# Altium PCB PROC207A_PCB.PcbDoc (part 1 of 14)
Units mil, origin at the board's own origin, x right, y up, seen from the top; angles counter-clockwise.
Board outline 4094.49 x 3724.79 mil, 8 copper layers (Top Layer, L2_GND1, L3_SIG1, L4_PWR1, L5_PWR2, L6_SIG2, L7_GND2, Bottom Layer), stack 58.1 mil thick; 584 components, 399 nets, 8440 pads, 5258 vias.
Unrouted connection lines stored in the file: 9.
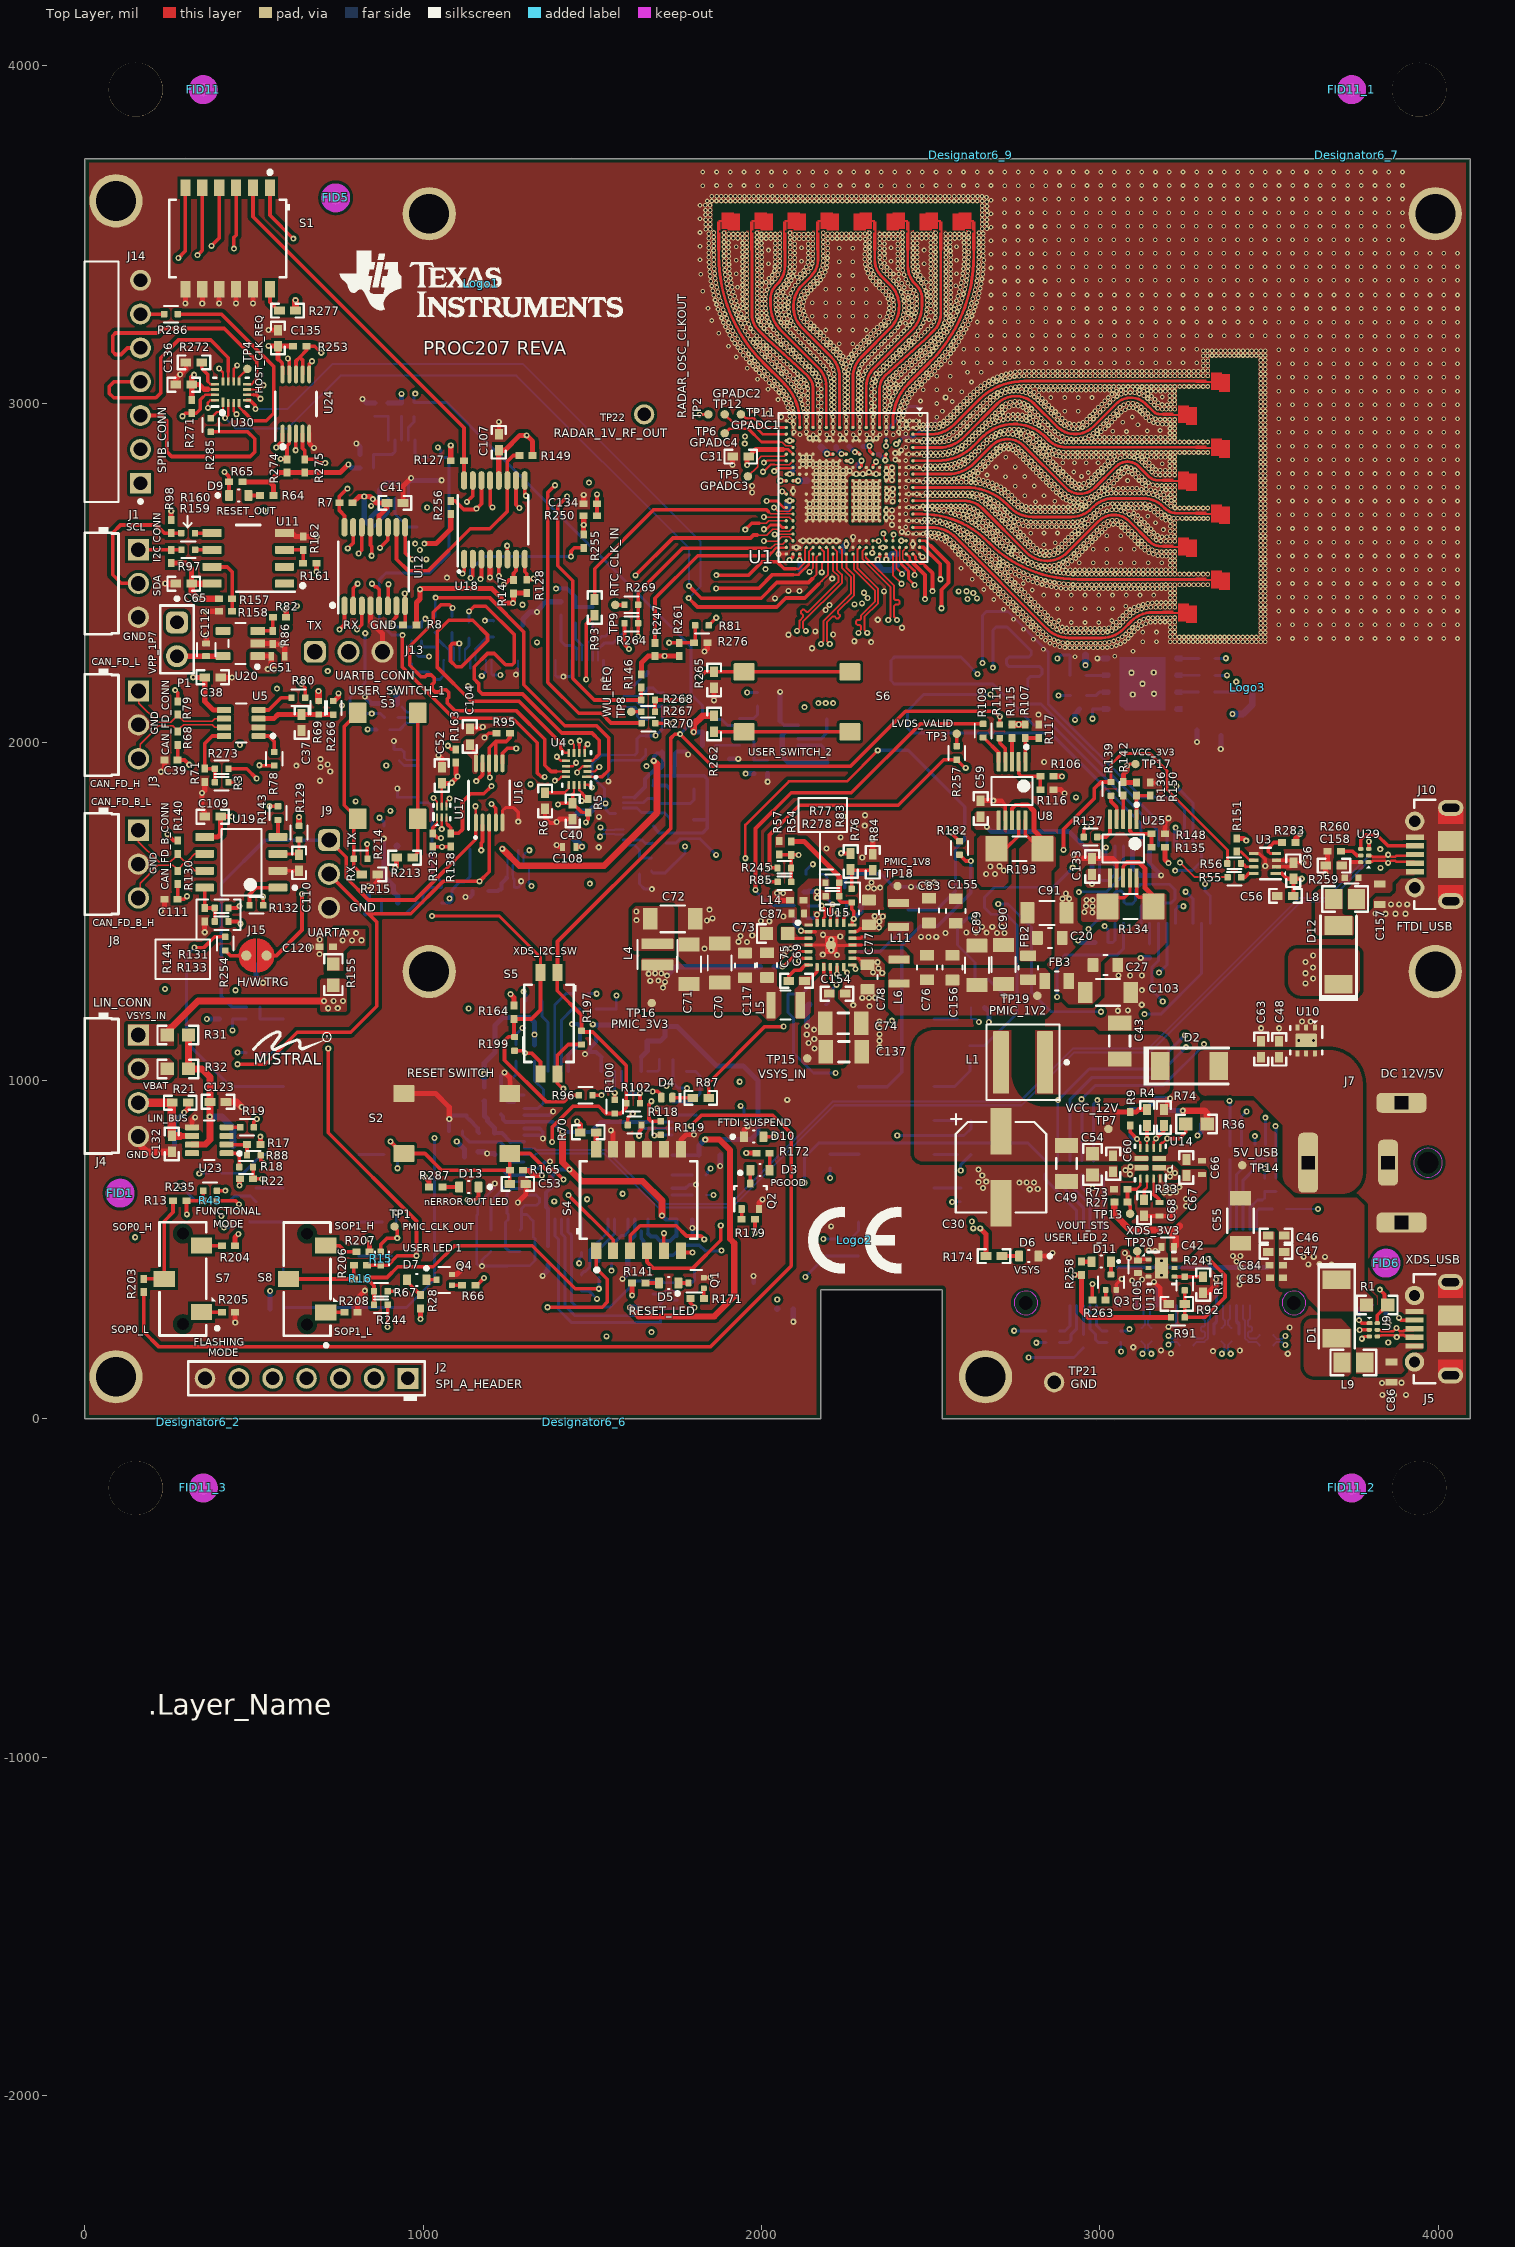
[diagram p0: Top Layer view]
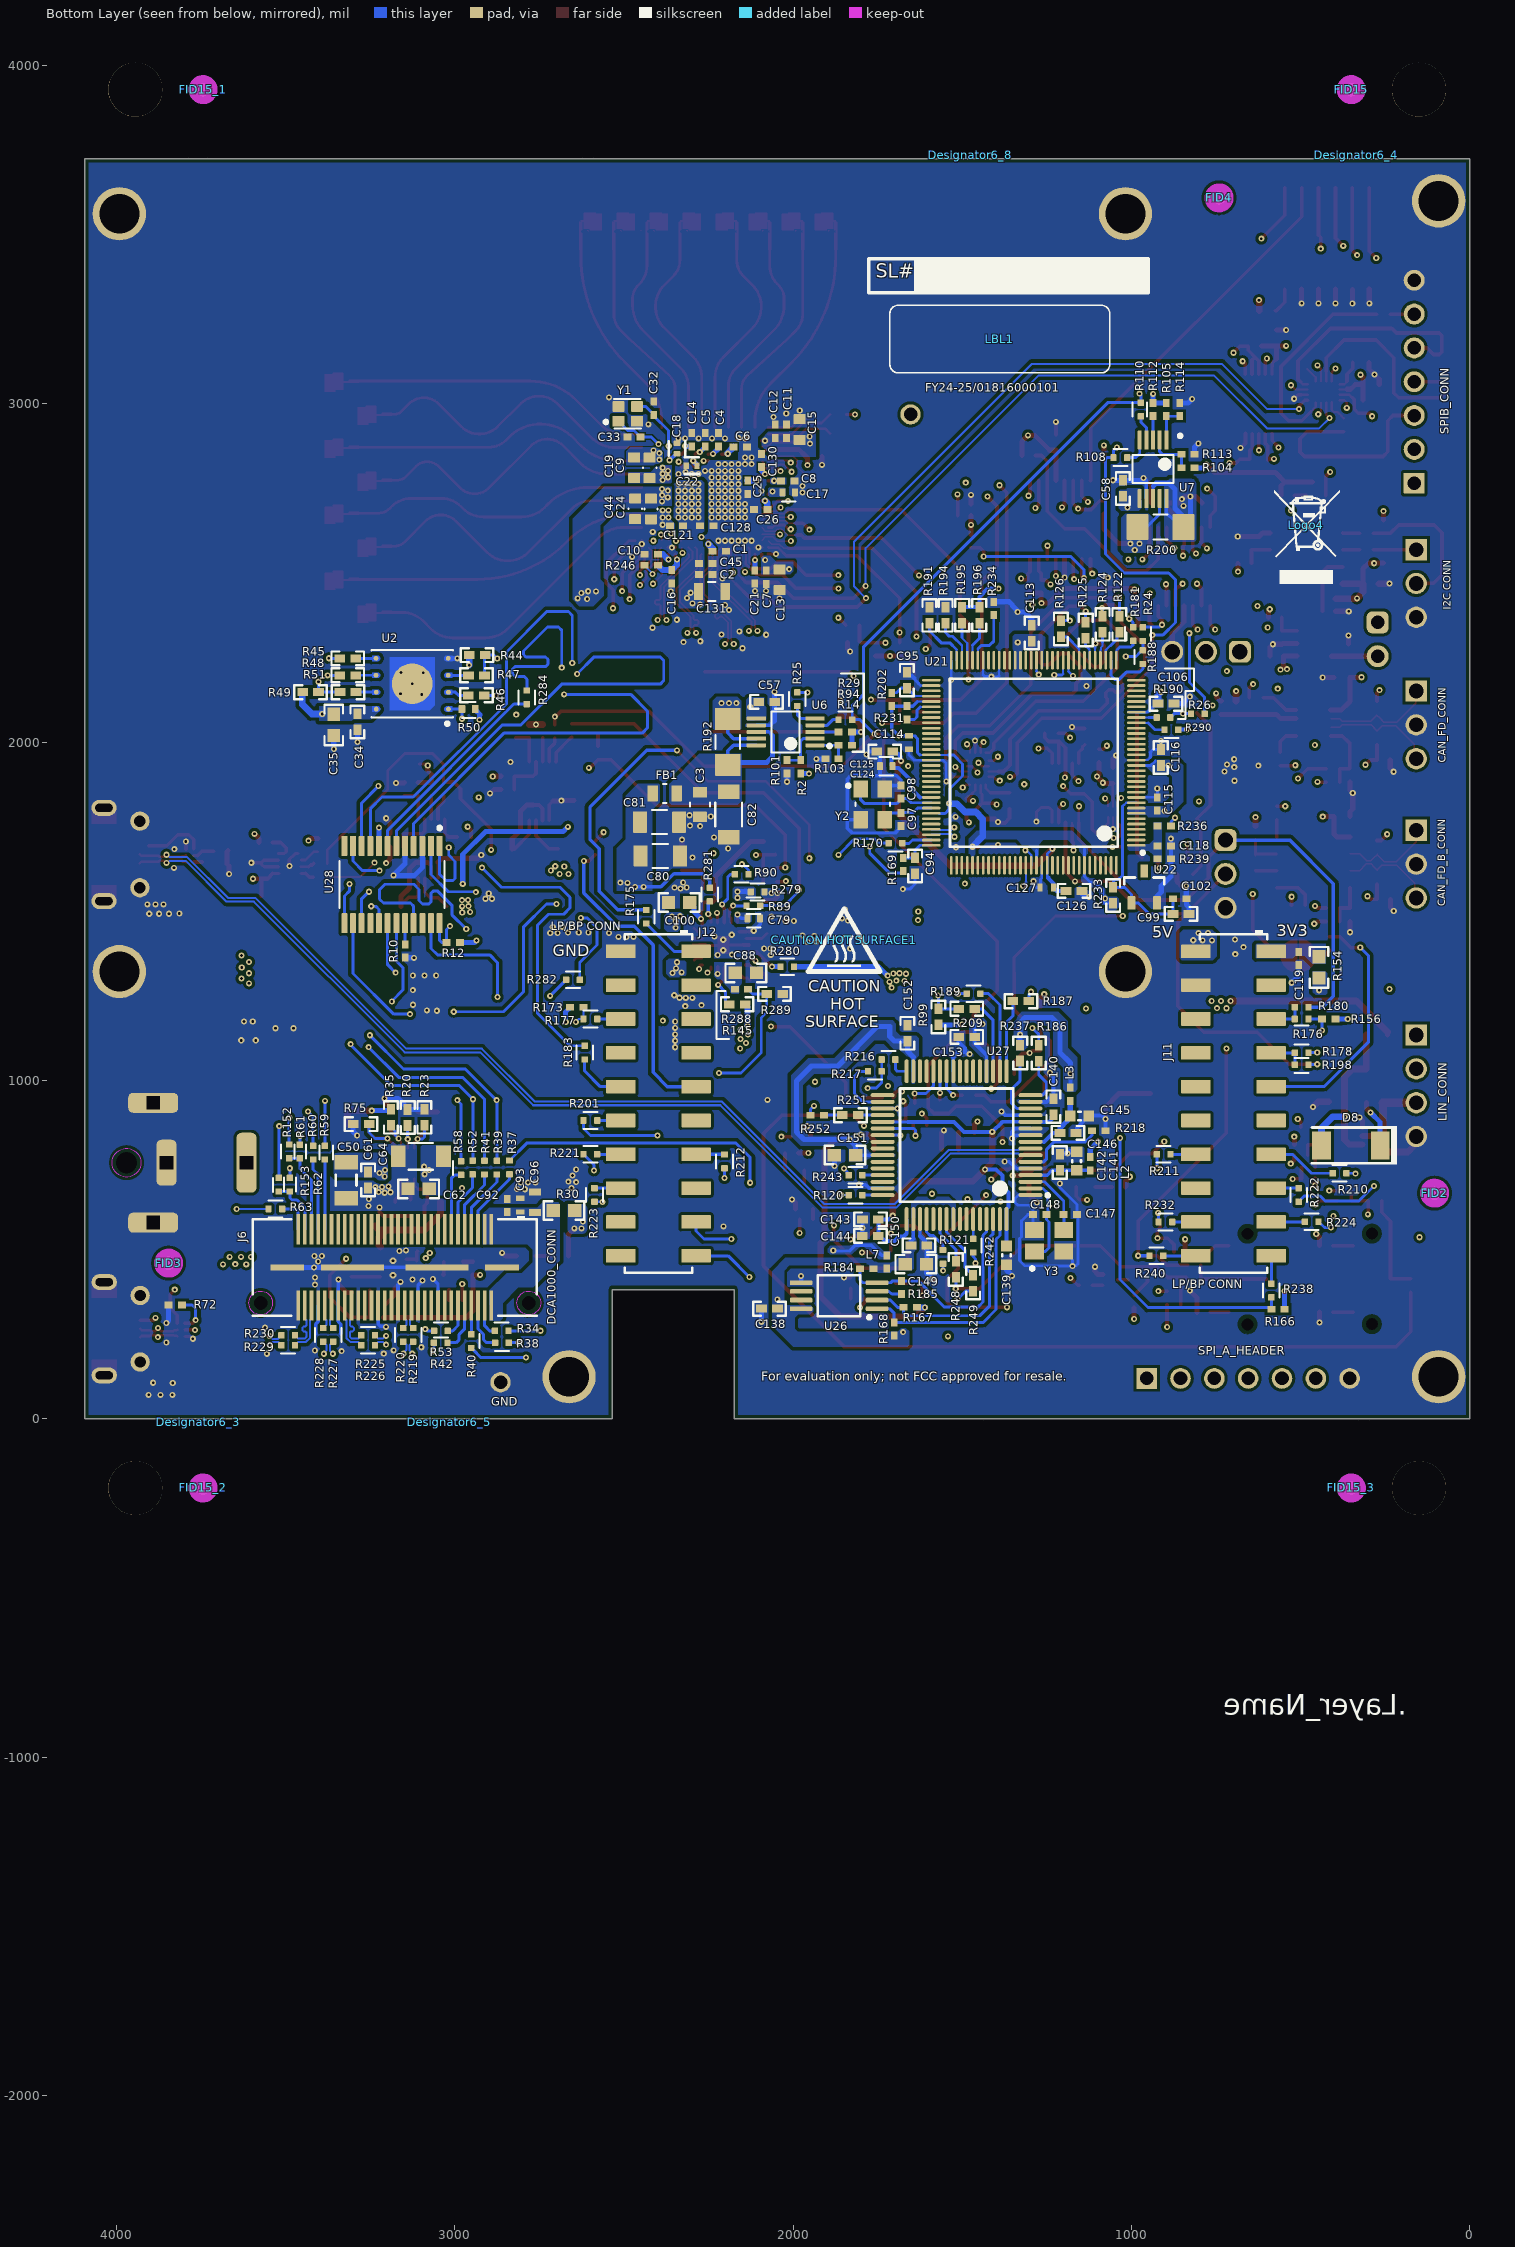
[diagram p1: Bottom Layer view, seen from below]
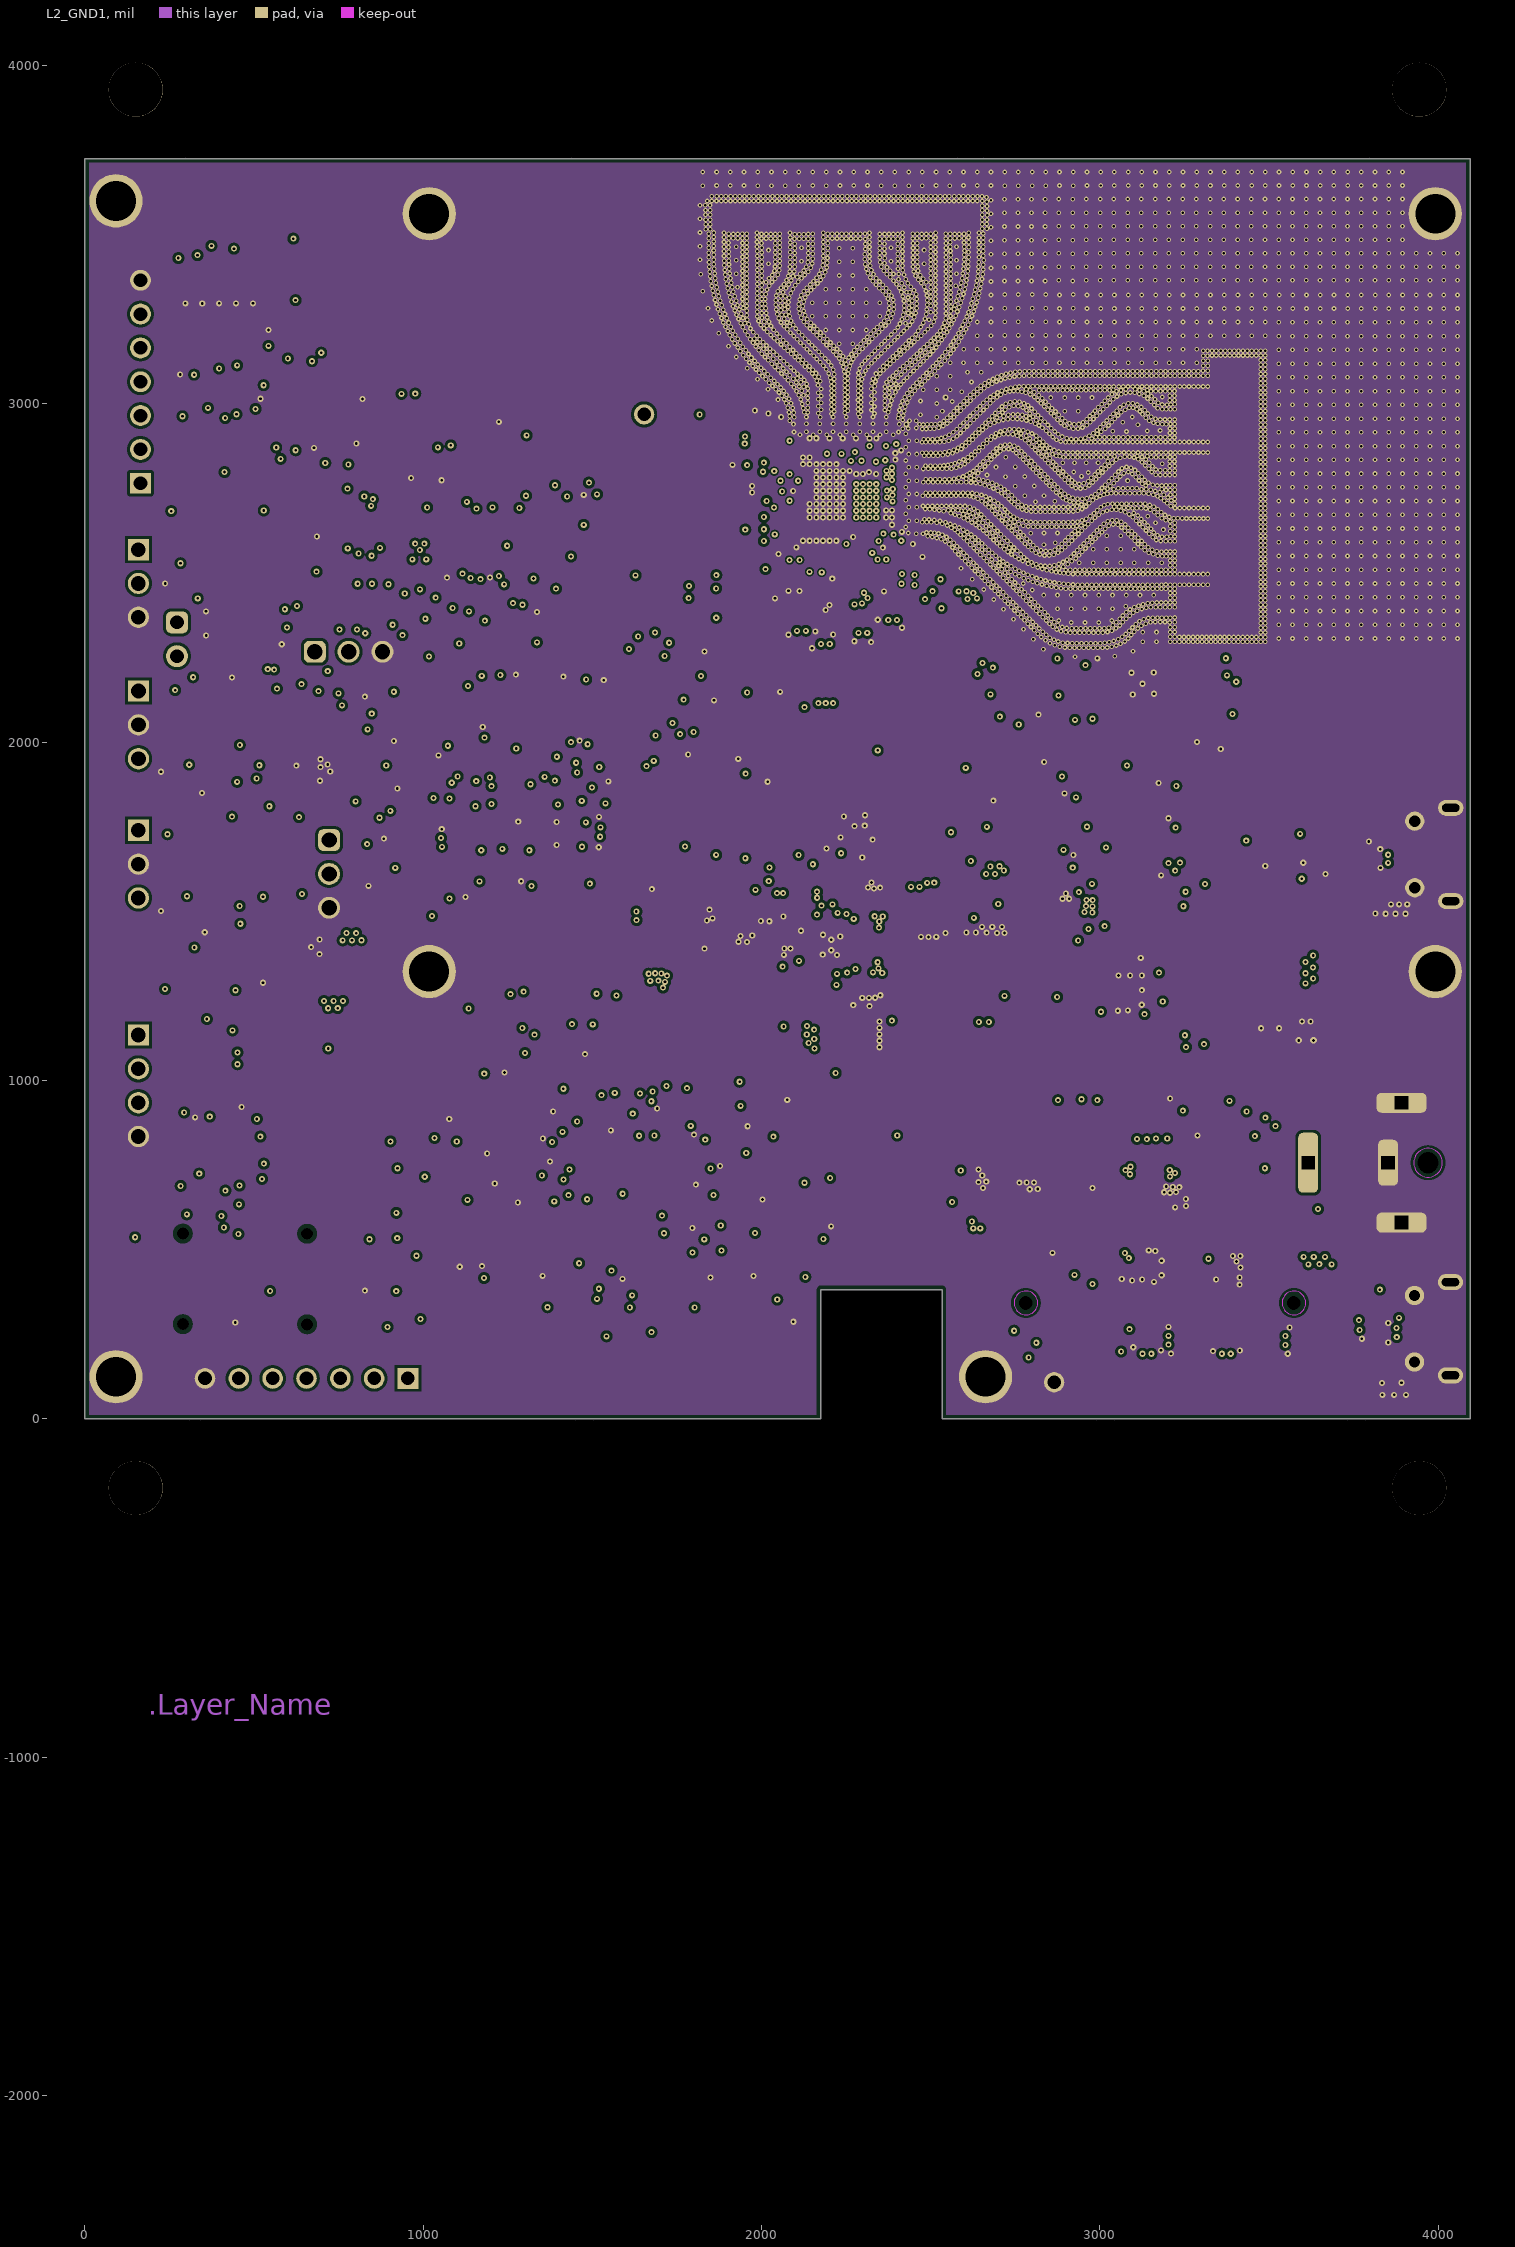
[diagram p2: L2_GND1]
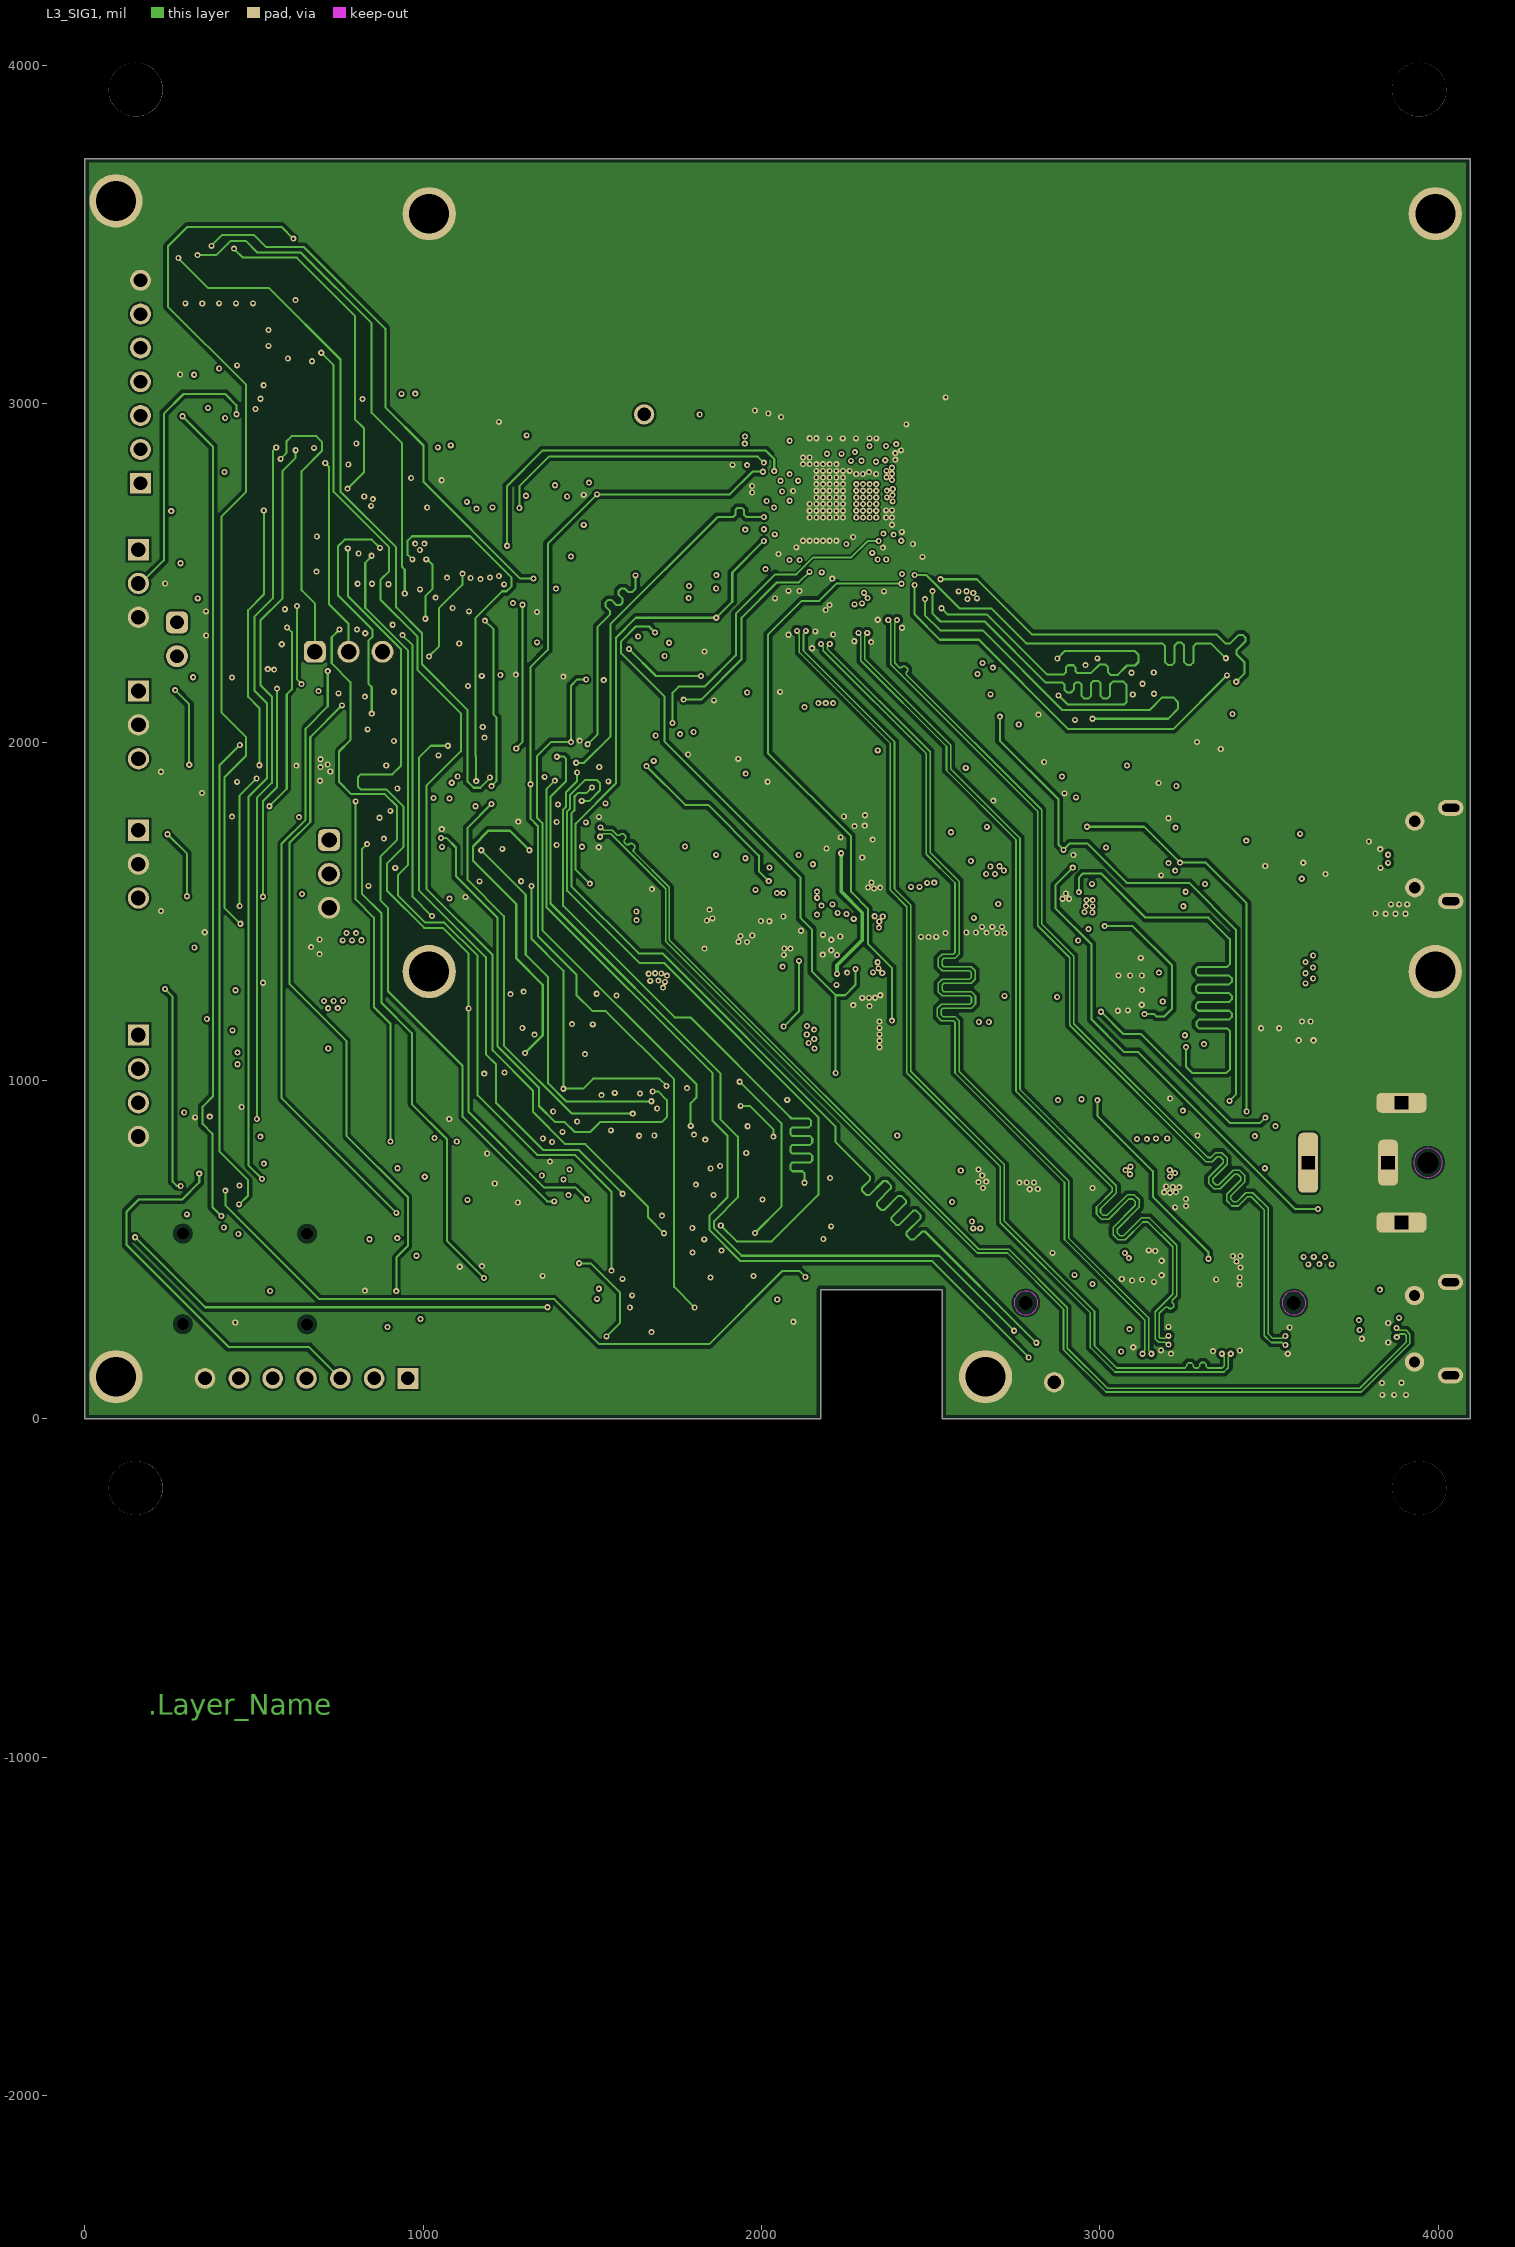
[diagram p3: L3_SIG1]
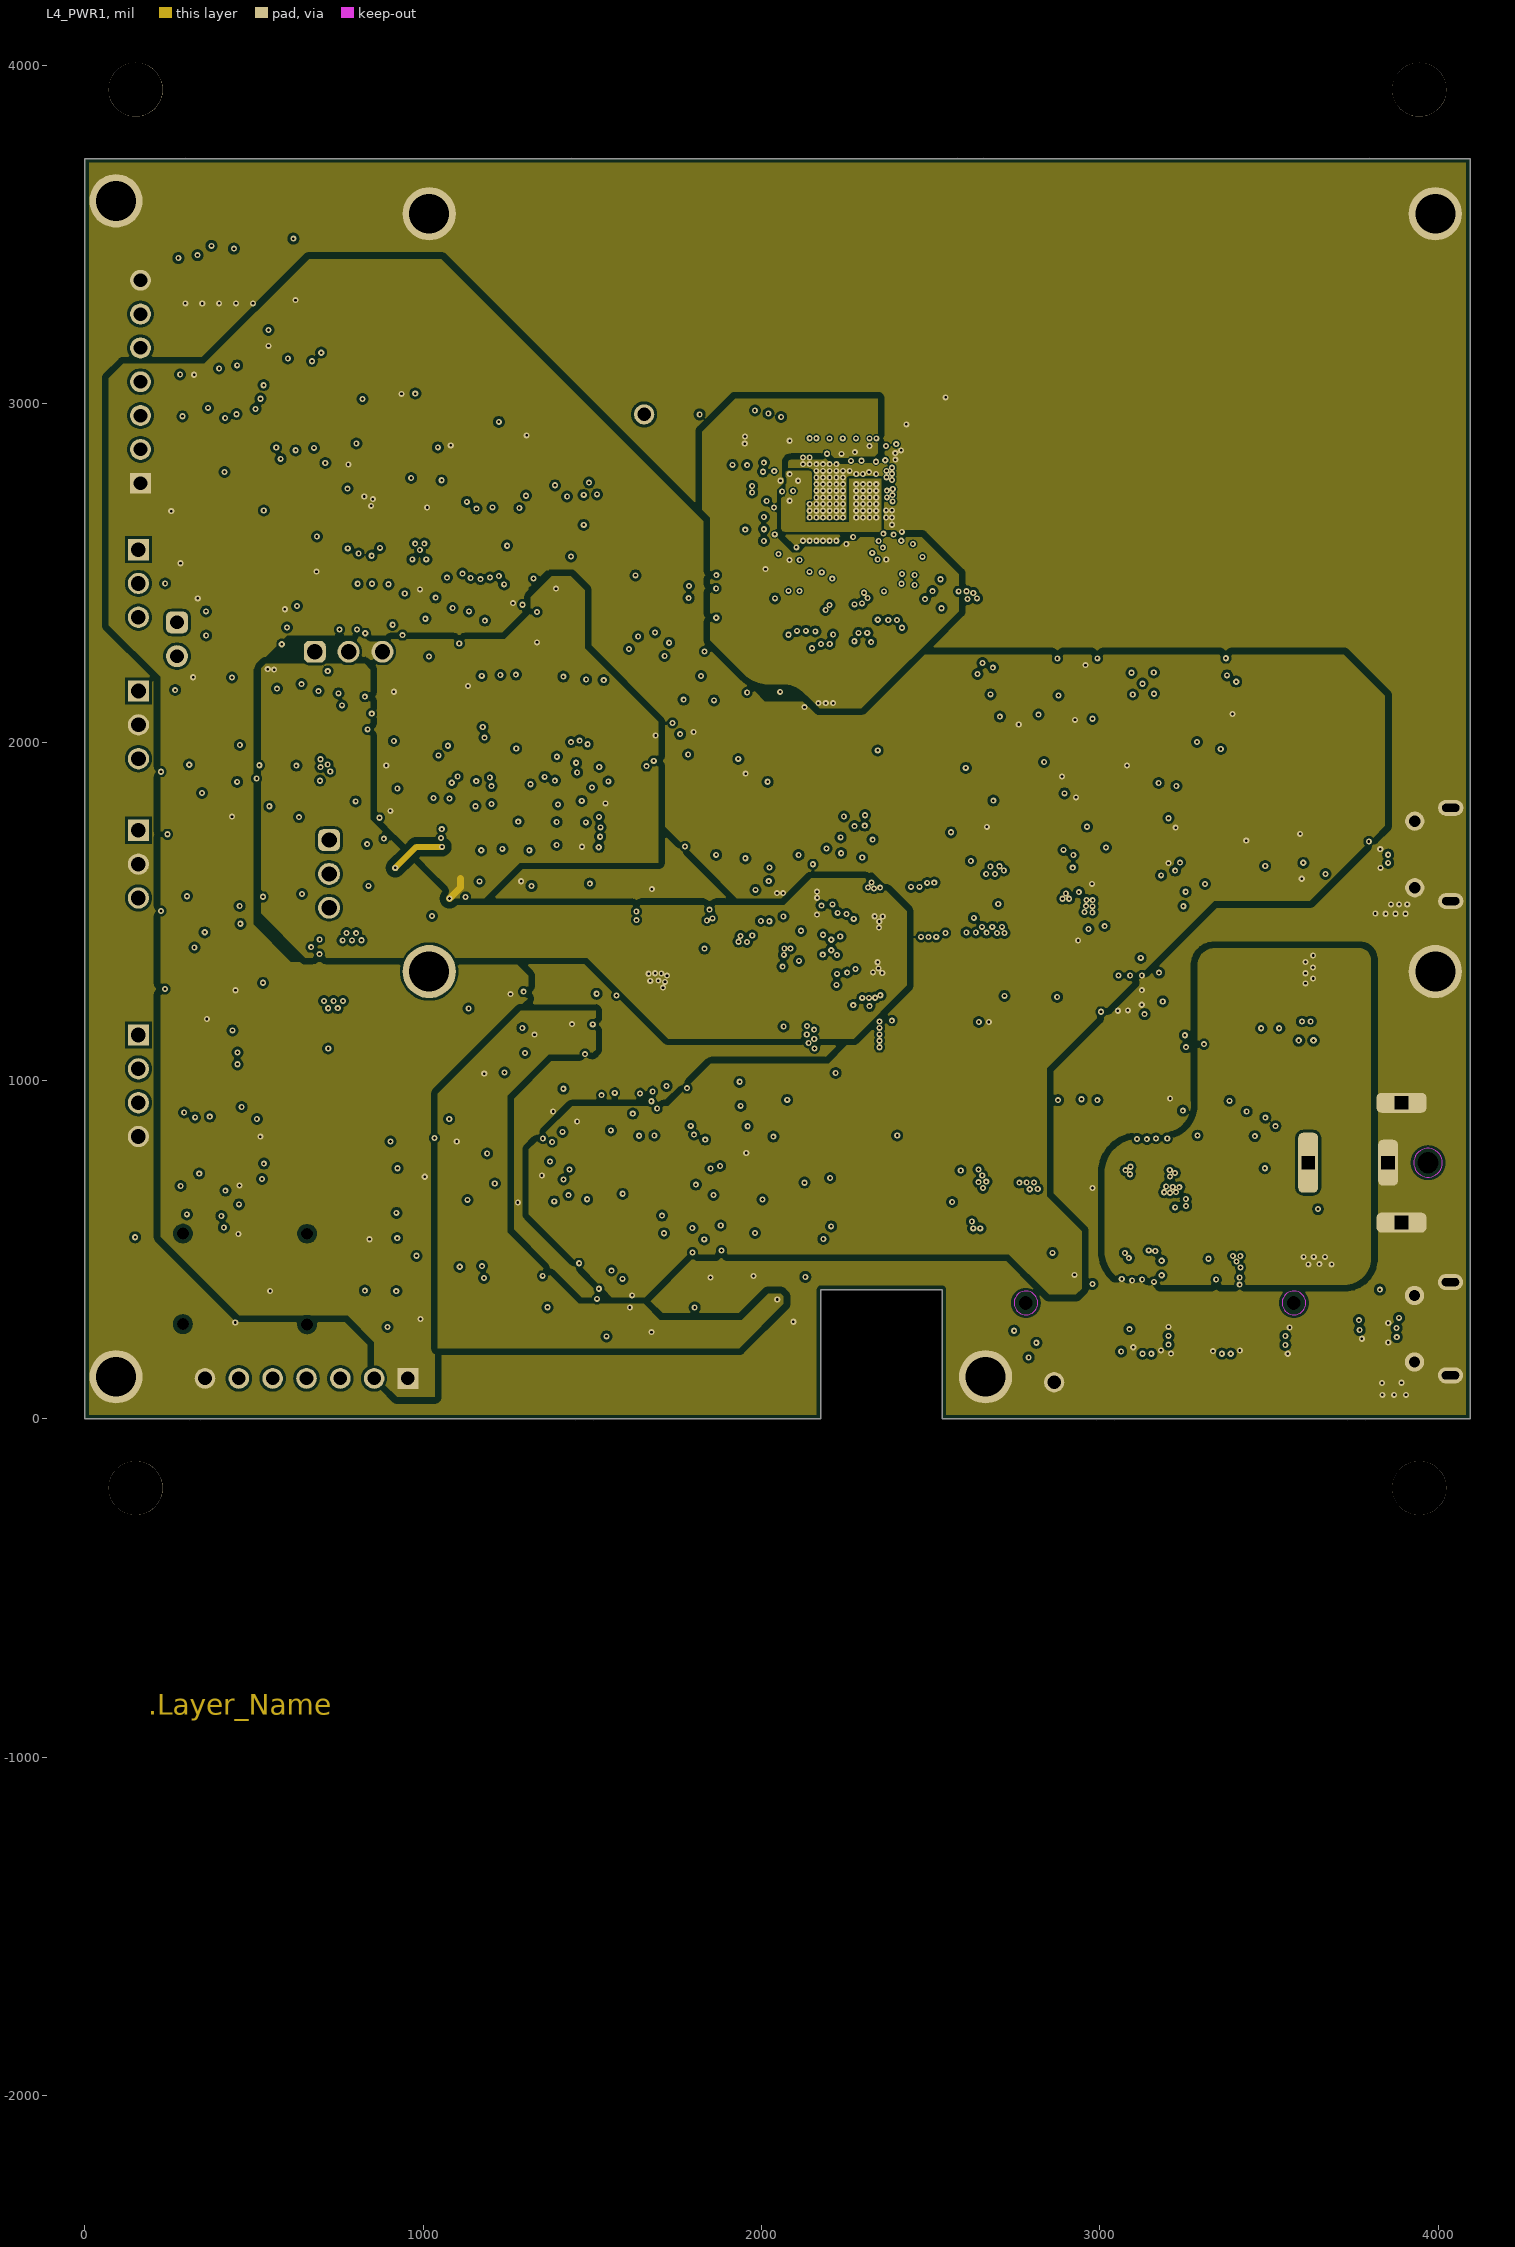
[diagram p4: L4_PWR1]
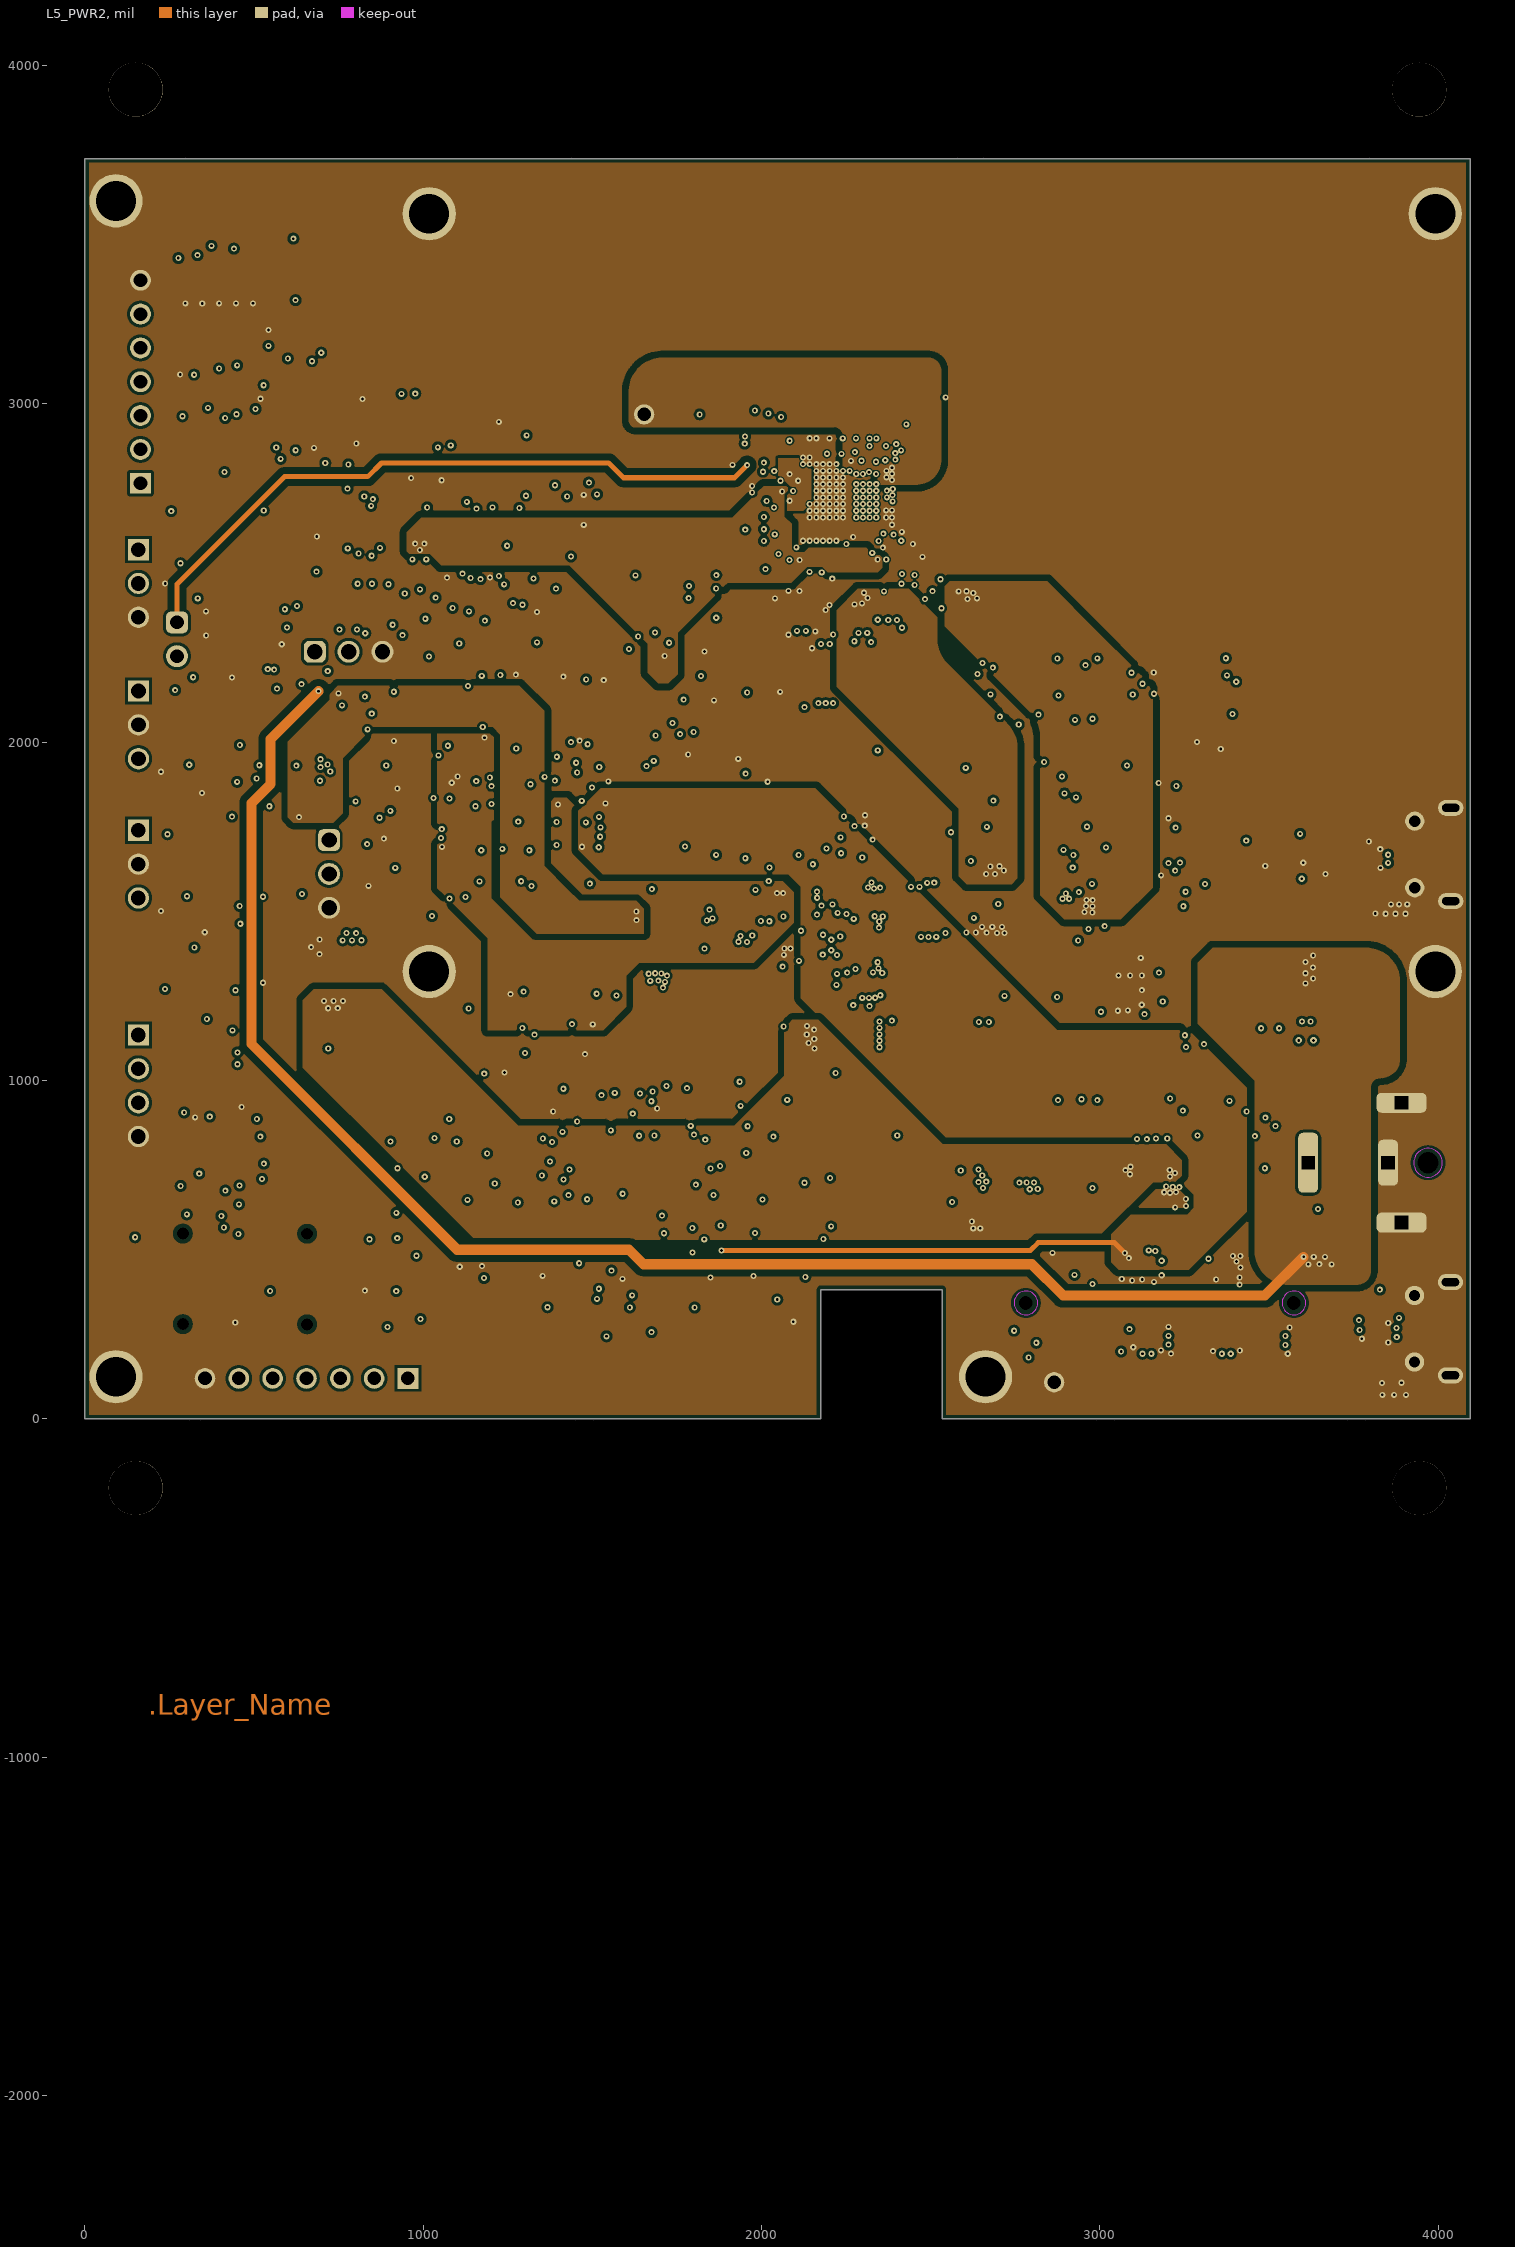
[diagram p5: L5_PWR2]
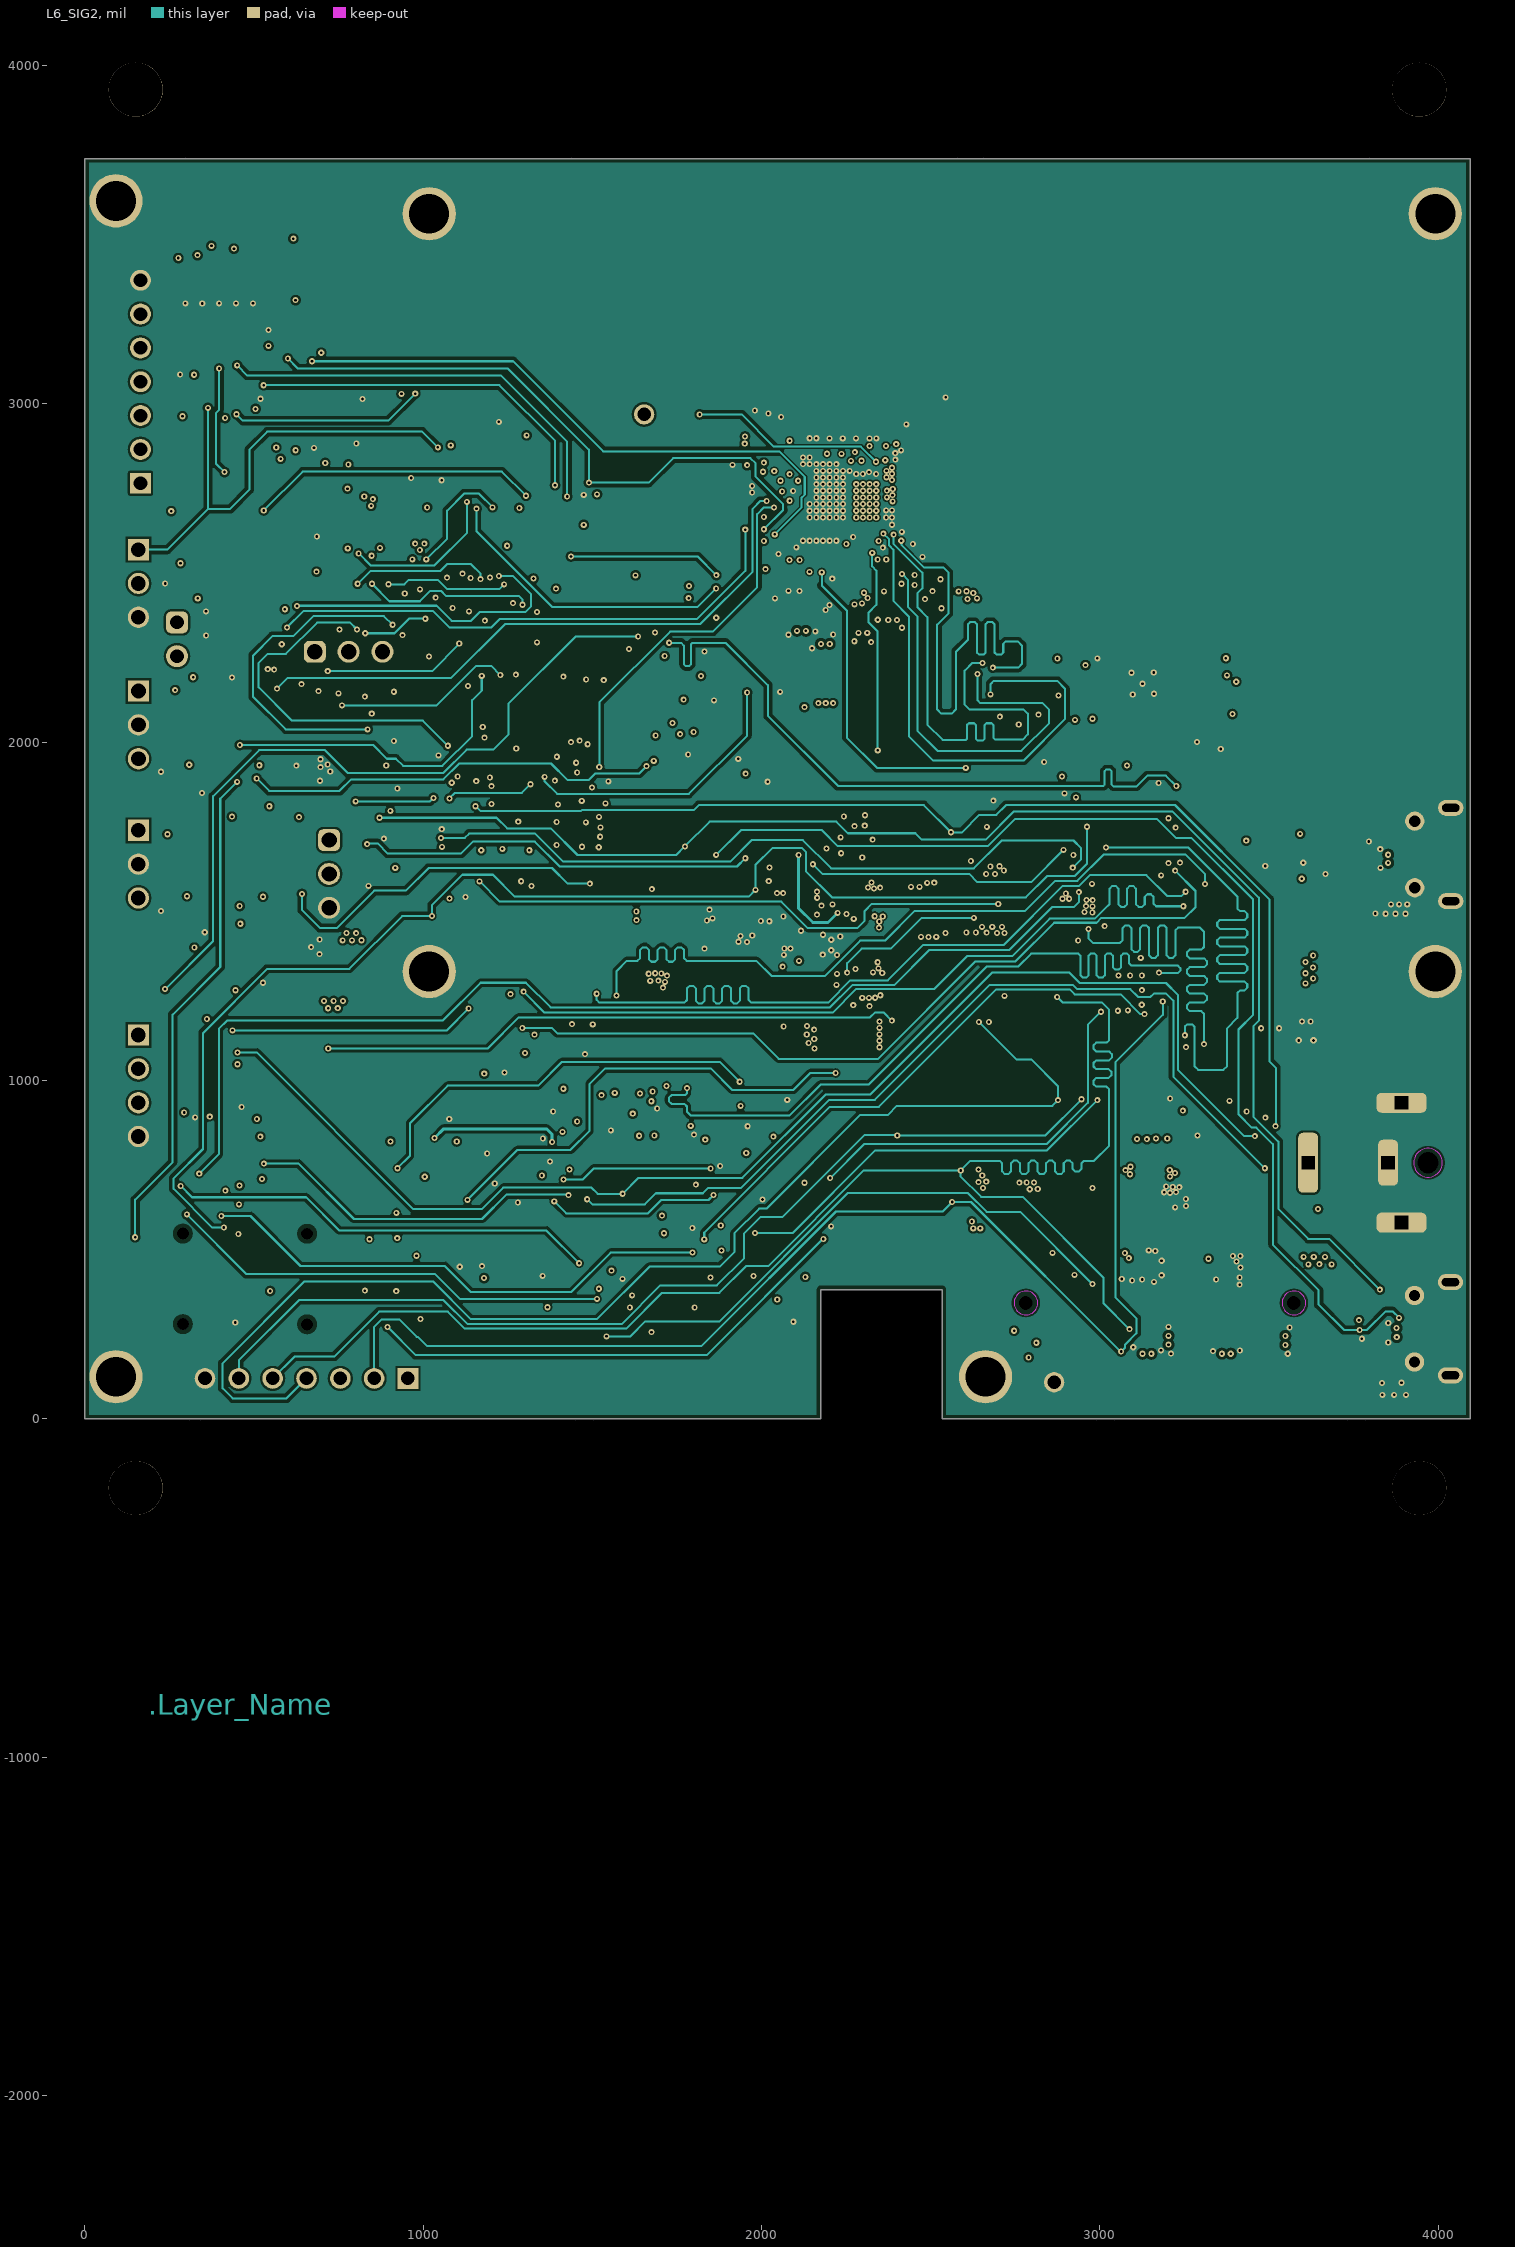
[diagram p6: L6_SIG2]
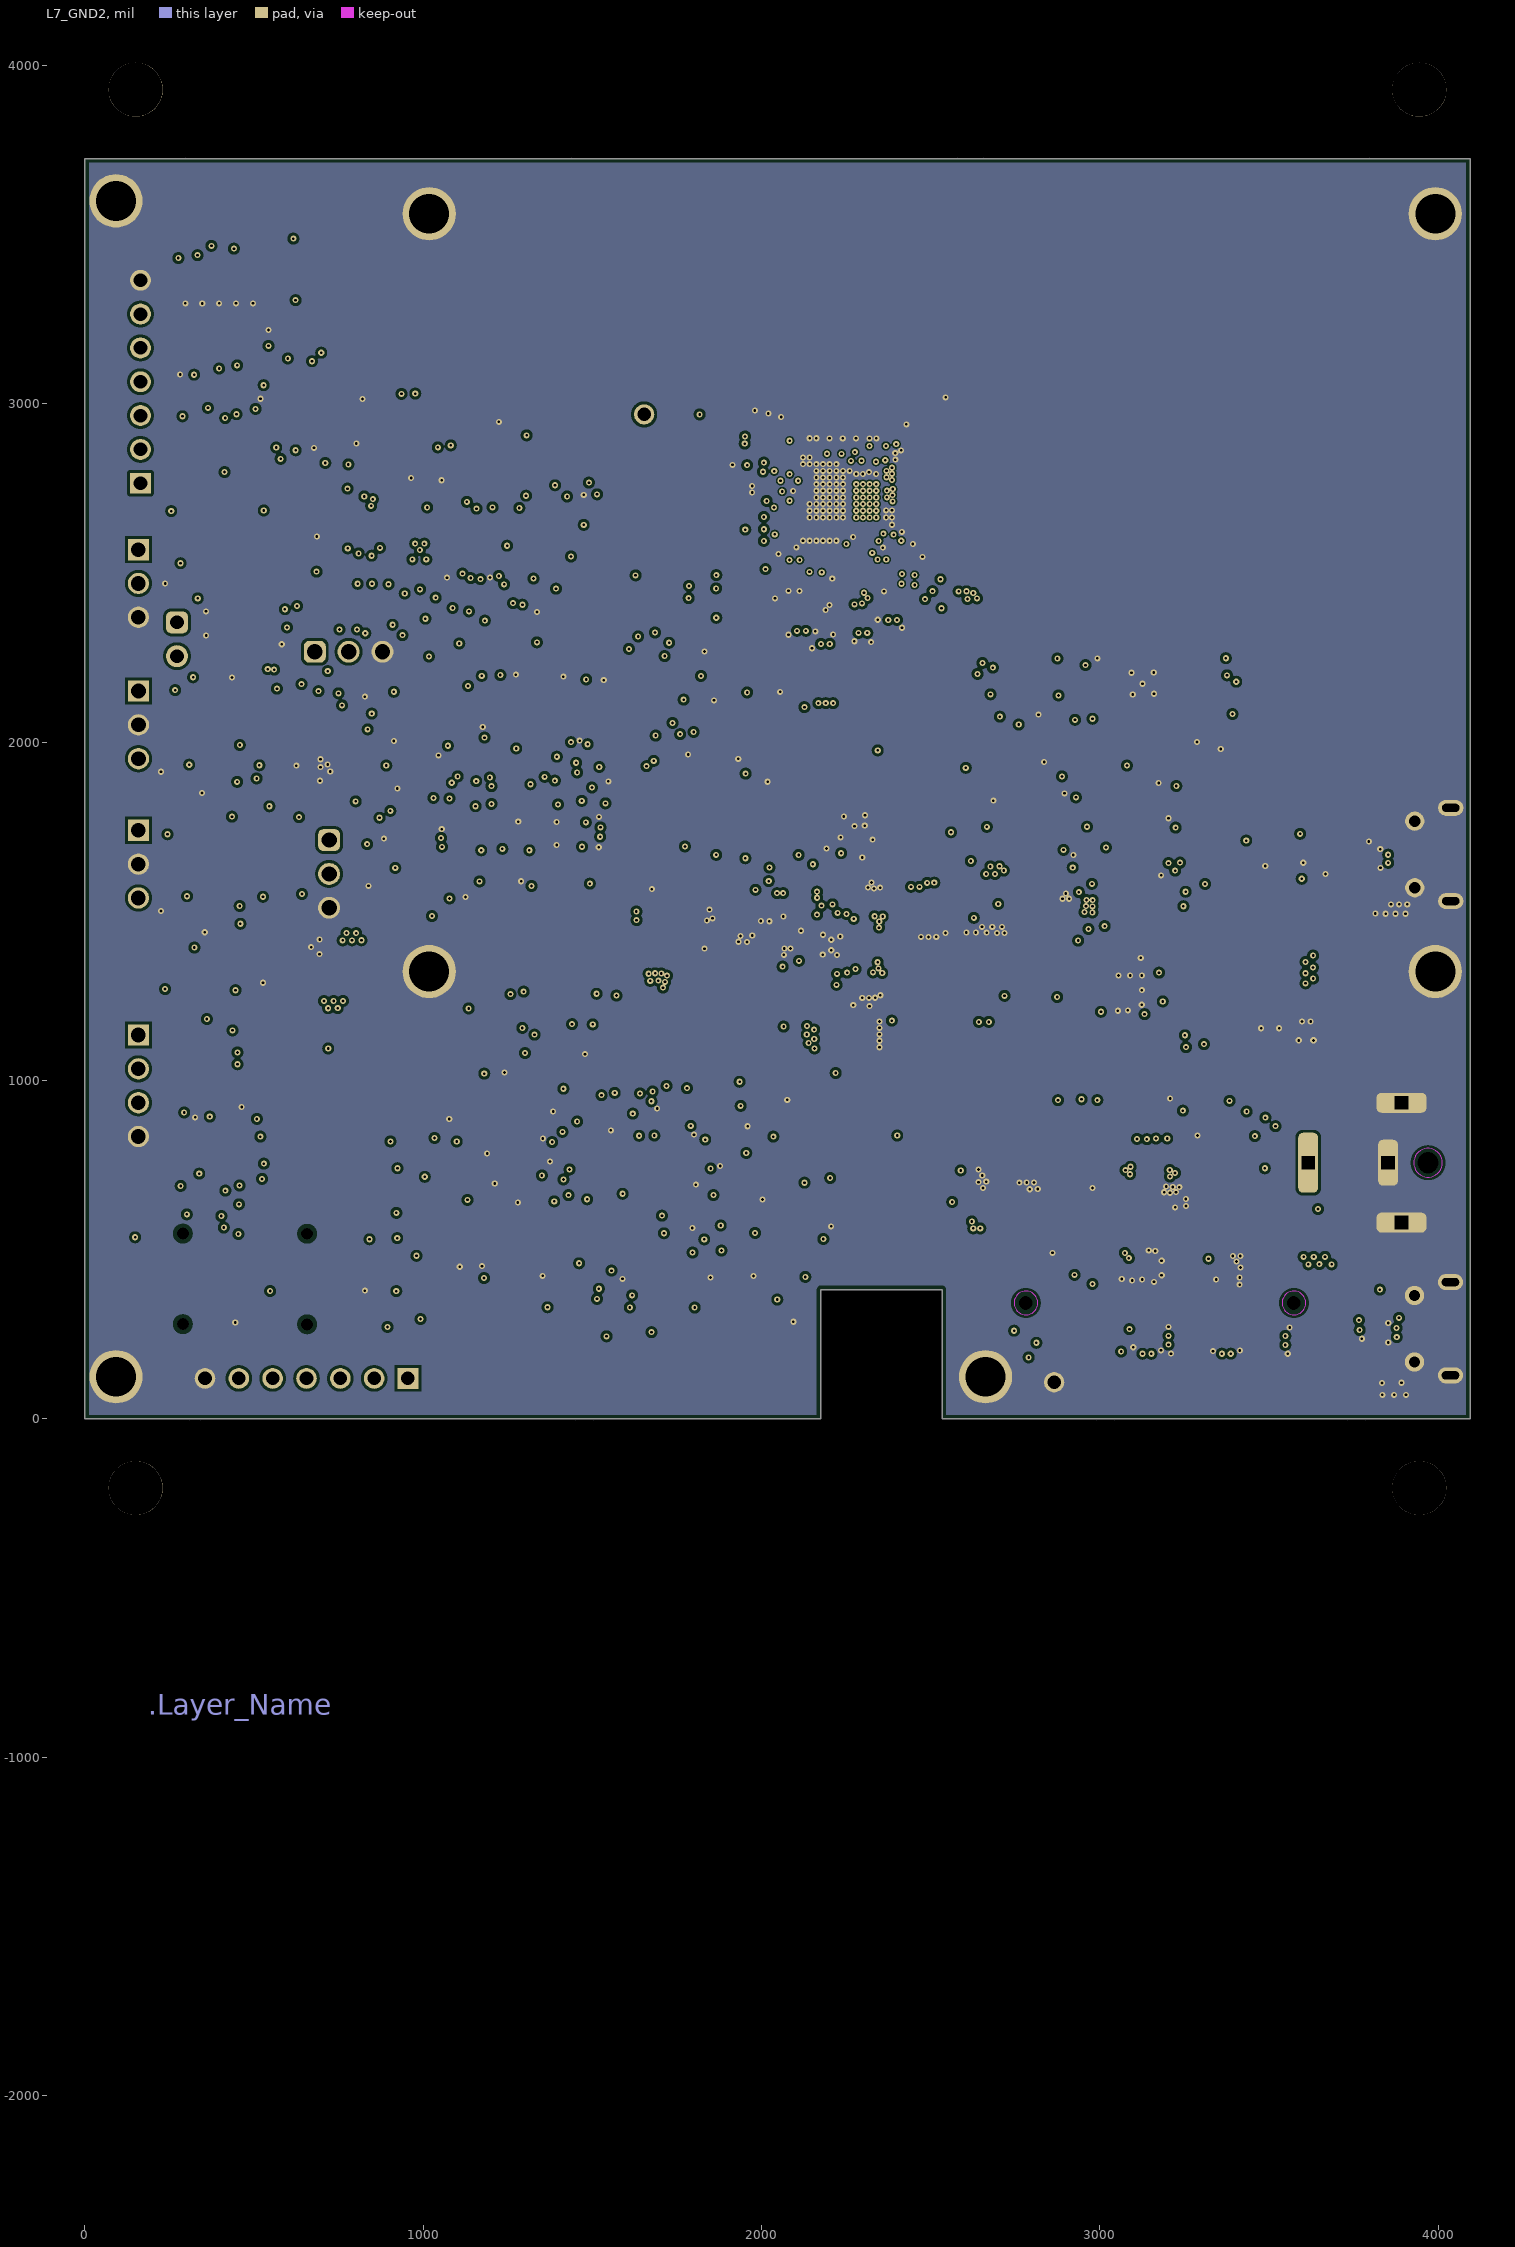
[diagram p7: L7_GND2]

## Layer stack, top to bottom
Top Solder: solder mask 0.8, Solder Resist, Dk 1
Top Layer: signal copper 1.6
Dielectric 1: core 5, RO3003, Dk 3
L2_GND1: signal copper 1.4
Dielectric 2: prepreg 5.5, PCL370HR, Dk 3.9
L3_SIG1: signal copper 1.4
Dielectric 3: core 10, PCL370HR, Dk 4.25
L4_PWR1: signal copper 1.4
Dielectric 4: prepreg 5.5, PCL370HR, Dk 3.9
L5_PWR2: signal copper 1.4
Dielectric 5: prepreg 10, PCL370HR, Dk 4.25
L6_SIG2: signal copper 1.4
Dielectric 6: core 5.5, PCL370HR, Dk 3.9
L7_GND2: signal copper 1.4
Dielectric 7: core 5, PCL370HR, Dk 4.25
Bottom Layer: signal copper 1.6
Bottom Solder: solder mask 0.8, Solder Resist, Dk 1

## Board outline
0,0 0,3724.79 4094.49,3724.79 4094.49,0 2534.49,0 2534.49,381.95 2174.49,381.95 2174.49,0

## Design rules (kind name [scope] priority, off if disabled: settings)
AcuteAngle [All] p1 off: minimum=4.50000000000000E+0001 checktracksonly=FALSE
AssemblyTestPointUsage [All] p1: valid=2
BoardOutlineClearance [All] p1: gap=12 ignorepadtopadclearanceinfootprint=FALSE
Clearance Diff_DRC_Clear [InAnyDifferentialPair vs InAnyDifferentialPair] p1: gap=3 ignorepadtopadclearanceinfootprint=TRUE except(0: Poly-Region)
Clearance "Clearance_TX and RX" [InNetClass('TX and RX')] p2: gap=3.94 ignorepadtopadclearanceinfootprint=FALSE except(0: Poly-Region; 4: Arc-Text Track-Text SMDPad-Text THPad-Text Via-Text Fill-Text Poly-Text Region-Text Text-Text; 4.92: SMDPad-Poly; 6: Arc-Hole Track-Hole SMDPad-Via SMDPad-Hole THPad-Hole Via-Hole Fill-Hole Poly-Hole Region-Hole Text-Hole; 7.7: Fill-Fill Fill-Poly; 8: Arc-Arc Arc-Track Track-Track SMDPad-Fill SMDPad-Region THPad-Fill THPad-Poly THPad-Region Via-Via Via-Fill Via-Poly; 9: SMDPad-SMDPad; 10: Arc-SMDPad Arc-THPad Track-SMDPad Track-THPad SMDPad-THPad THPad-THPad THPad-Via)
Clearance Clearance_BGA [WithinRoom('BGA1')] p3: gap=4 ignorepadtopadclearanceinfootprint=FALSE except(8: Fill-Fill Fill-Poly Fill-Region Poly-Poly Poly-Region Region-Region)
Clearance 90E_Inner_layer_diff [InDifferentialPairClass('90E') vs InLayerClass('External_layers') or InLayerClass('Inner_sig_layer')] p4: gap=8 ignorepadtopadclearanceinfootprint=TRUE except(0: Text-Hole; 5: Track-SMDPad; 6: Track-Via; 10: Track-Poly Fill-Fill Fill-Poly Fill-Region Poly-Poly Poly-Region Region-Region; 11: Fill-Hole Poly-Hole Region-Hole; 12: Track-Track Track-THPad)
Clearance 100E_Inner_layer [InDifferentialPairClass('100E') vs InLayerClass('Inner_sig_layer')] p5: gap=8 ignorepadtopadclearanceinfootprint=TRUE except(0: Text-Hole; 10: Track-Poly Fill-Fill Fill-Poly Fill-Region Poly-Poly Poly-Region Region-Region; 11: Fill-Hole Poly-Hole Region-Hole; 12: Track-Track Track-SMDPad Track-THPad)
Clearance 100E_OUTER_LAYER [InDifferentialPairClass('100E') vs InLayerClass('External_layers')] p6: gap=8 ignorepadtopadclearanceinfootprint=TRUE except(0: Text-Hole; 10: Track-Poly Fill-Fill Fill-Poly Fill-Region Poly-Poly Poly-Region Region-Region; 11: Fill-Hole Poly-Hole Region-Hole; 12: Track-SMDPad Track-THPad; 20: Track-Track)
Clearance 90E_Inner_layer [InDifferentialPairClass('90E') vs InLayerClass('Inner_sig_layer')] p7: gap=8 ignorepadtopadclearanceinfootprint=TRUE except(0: Text-Hole; 10: Track-Track Track-Poly Fill-Fill Fill-Poly Fill-Region Poly-Poly Poly-Region Region-Region; 11: Fill-Hole Poly-Hole Region-Hole; 12: Track-SMDPad Track-THPad)
Clearance Clearance_fiducials [InComponentClass('FiducialMark')] p8: gap=8 ignorepadtopadclearanceinfootprint=TRUE except(0: Arc-SMDPad Text-Hole; 5: Via-Region Region-Region; 5.5: Track-Track; 6: Track-SMDPad Track-Via SMDPad-SMDPad SMDPad-Via; 10: Track-Poly Fill-Fill Fill-Poly Fill-Region Poly-Poly Poly-Region; 11: Fill-Hole Poly-Hole Region-Hole)
Clearance Clearance_BOTTOM [OnBottomLayer] p9: gap=8 ignorepadtopadclearanceinfootprint=TRUE except(0: Text-Hole; 3.9: Track-Track; 6: Track-SMDPad; 10: Track-Poly Fill-Fill Fill-Poly Fill-Region Poly-Poly Poly-Region Region-Region; 11: Fill-Hole Poly-Hole Region-Hole)
Clearance Clearance_TOP [OnTopLayer] p10: gap=8 ignorepadtopadclearanceinfootprint=TRUE except(0: Text-Hole; 5: Via-Region Region-Region; 5.5: Track-Track; 6: Track-SMDPad Track-Via SMDPad-SMDPad SMDPad-Via; 10: Track-Poly Fill-Fill Fill-Poly Fill-Region Poly-Poly Poly-Region; 11: Fill-Hole Poly-Hole Region-Hole)
Clearance Clearance_INNER_LAYER [(OnLayer('L3_SIG1') OR OnLayer('L6_SIG2'))] p11: gap=6 ignorepadtopadclearanceinfootprint=TRUE except(0: Text-Hole; 10: Track-Poly Fill-Fill Fill-Poly Fill-Region Poly-Poly Poly-Region Region-Region; 11: Fill-Hole Poly-Hole Region-Hole)
Clearance [All] p12: gap=8 ignorepadtopadclearanceinfootprint=TRUE except(0: Text-Hole; 6: Arc-Hole Track-Track Track-Text Track-Hole; 10: Fill-Fill Fill-Poly Fill-Region Poly-Region Region-Region; 11: Fill-Hole Poly-Hole Region-Hole; 20: Track-Poly Poly-Poly)
Clearance Clearance_Keepout [IsKeepOut] p13: gap=0 ignorepadtopadclearanceinfootprint=TRUE
ComponentClearance ComponentClearance_MatingCon-3D [All vs not InAnyComponent] p1: gap=0 collisioncheckmode=3 verticalgap=0 showdistances=FALSE
ComponentClearance "ComponentClearance_WEE Logo" [InComponent('Logo4')] p2: gap=0 collisioncheckmode=3 verticalgap=0 showdistances=TRUE
ComponentClearance ComponentClearance_R77 [InComponent('R77') vs InComponent('Logo1')] p3: gap=0 collisioncheckmode=3 verticalgap=0 showdistances=TRUE
ComponentClearance ComponentClearance_Logo [InComponentClass('Logo')] p4: gap=0 collisioncheckmode=3 verticalgap=0 showdistances=TRUE
ComponentClearance "ComponentClearance_Mounting Holes_Fiducial Marks" [InComponentClass('FiducialMark') vs InPadClass('Mounting Holes PADS')] p5: gap=50 collisioncheckmode=3 verticalgap=10 showdistances=TRUE
ComponentClearance [All] p6: gap=6 collisioncheckmode=3 verticalgap=10 showdistances=TRUE
DiffPairsRouting 120E [InDifferentialPairClass('120E')] p1: maxlimit=10 minlimit=5.5 mostfreqgap=10 toplayer_maxgap=5.5 toplayer_prefgap=5.5 toplayer_minwidth=4.3 toplayer_maxwidth=4.3 toplayer_prefwidth=4.3 midlayer1_mingap=10 midlayer1_minwidth=15 midlayer1_maxwidth=15 midlayer1_prefwidth=15 midlayer2_mingap=9.8 midlayer2_maxgap=9.8 midlayer2_prefgap=9.8 midlayer2_minwidth=3.1 midlayer2_maxwidth=3.1 midlayer2_prefwidth=3.1 midlayer3_mingap=10 midlayer3_minwidth=15 midlayer3_maxwidth=15 midlayer3_prefwidth=15 midlayer4_mingap=10 midlayer4_minwidth=15 midlayer4_maxwidth=15 midlayer4_prefwidth=15 midlayer5_mingap=10 midlayer5_minwidth=15 midlayer5_maxwidth=15 midlayer5_prefwidth=15 midlayer6_mingap=9.8 midlayer6_maxgap=9.8 midlayer6_prefgap=9.8 midlayer6_minwidth=3.1 midlayer6_maxwidth=3.1 midlayer6_prefwidth=3.1 bottomlayer_mingap=5.9 bottomlayer_maxgap=5.9 bottomlayer_prefgap=5.9 bottomlayer_minwidth=4.7 bottomlayer_maxwidth=4.7 bottomlayer_prefwidth=4.7 maxuncoupledlength=500
DiffPairsRouting 100E [InDifferentialPairClass('100E')] p2: maxlimit=10 minlimit=3.9 mostfreqgap=10 toplayer_mingap=4.2 toplayer_maxgap=4.2 toplayer_prefgap=4.2 toplayer_minwidth=5.8 toplayer_maxwidth=5.8 toplayer_prefwidth=5.8 midlayer1_mingap=10 midlayer1_minwidth=15 midlayer1_maxwidth=15 midlayer1_prefwidth=15 midlayer2_mingap=7.2 midlayer2_maxgap=7.2 midlayer2_prefgap=7.2 midlayer2_minwidth=4.8 midlayer2_maxwidth=4.8 midlayer2_prefwidth=4.8 midlayer3_mingap=10 midlayer3_minwidth=15 midlayer3_maxwidth=15 midlayer3_prefwidth=15 midlayer4_mingap=10 midlayer4_minwidth=15 midlayer4_maxwidth=15 midlayer4_prefwidth=15 midlayer5_mingap=10 midlayer5_minwidth=15 midlayer5_maxwidth=15 midlayer5_prefwidth=15 midlayer6_mingap=7.2 midlayer6_maxgap=7.2 midlayer6_prefgap=7.2 midlayer6_minwidth=4.8 midlayer6_maxwidth=4.8 midlayer6_prefwidth=4.8 bottomlayer_maxgap=3.9 bottomlayer_prefgap=3.9 bottomlayer_minwidth=5.9 bottomlayer_maxwidth=5.9 bottomlayer_prefwidth=5.9 maxuncoupledlength=500
DiffPairsRouting 90E [InDifferentialPairClass('90E')] p3: maxlimit=10 minlimit=4 mostfreqgap=10 toplayer_maxgap=4 toplayer_prefgap=4 toplayer_minwidth=7.5 toplayer_maxwidth=7.5 toplayer_prefwidth=7.5 midlayer1_mingap=10 midlayer1_minwidth=15 midlayer1_maxwidth=15 midlayer1_prefwidth=15 midlayer2_mingap=5.9 midlayer2_maxgap=5.9 midlayer2_prefgap=5.9 midlayer2_minwidth=5 midlayer2_maxwidth=5 midlayer2_prefwidth=5 midlayer3_mingap=10 midlayer3_minwidth=15 midlayer3_maxwidth=15 midlayer3_prefwidth=15 midlayer4_mingap=10 midlayer4_minwidth=15 midlayer4_maxwidth=15 midlayer4_prefwidth=15 midlayer5_mingap=10 midlayer5_minwidth=15 midlayer5_maxwidth=15 midlayer5_prefwidth=15 midlayer6_mingap=5.9 midlayer6_maxgap=5.9 midlayer6_prefgap=5.9 midlayer6_minwidth=5 midlayer6_maxwidth=5 midlayer6_prefwidth=5 bottomlayer_mingap=5 bottomlayer_maxgap=5 bottomlayer_prefgap=5 bottomlayer_minwidth=6 bottomlayer_maxwidth=6 bottomlayer_prefwidth=6 maxuncoupledlength=500
FabricationTestPointUsage TestPointUsage [All] p1: valid=2 allowmultiple=FALSE
FabricationTestpoint Testpoint [All] p1: side=3 testpointundercomponent=TRUE minsize=40 maxsize=100 preferedsize=60 minholesize=0 maxholesize=40 preferedholesize=32 testpointgrid=1 allowsidetop=TRUE allowsidebottom=TRUE usegrid=TRUE gridtolerance=0.01
FanoutControl Fanout_LCC [IsLCC] p1: bgadir=Out bgaviamode=Centered fanoutstyle=Auto fanoutdirection=Alternating viagrid=1 // Fanout_LCC (Default Rule)
FanoutControl Fanout_BGA [IsBGA] p2: bgadir=Out bgaviamode=Centered fanoutstyle=Auto fanoutdirection=Alternating viagrid=1 // Fanout_BGA (Default Rule)
FanoutControl Fanout_Default [All] p4: bgadir=Out bgaviamode=Centered fanoutstyle=Auto fanoutdirection=Alternating viagrid=1 // Fanout_Default (Default Rule)
FanoutControl Fanout_Small [(CompPinCount < 5)] p5: bgadir=Out bgaviamode=Centered fanoutstyle=Auto fanoutdirection=OutThenIn viagrid=1 // Fanout_Small (Default Rule)
Height Room_Hieght [WithinRoom('Room_Hieght 1 MM')] p1: minheight=0 maxheight=41.34 prefheight=39.37
HoleSize [All] p1: absolutevalues=TRUE maxlimit=280 minlimit=5.9 maxpercent=80.000 minpercent=20.000
HoleToHoleClearance HoleToHoleClearance_1 [WithinRoom('BGA1')] p1: gap=4 allowstackedmicrovias=FALSE
MatchedLengths QSPI [InxSignalClass('QSPI')] p1: tolerance=10 checknetsindiffpair=FALSE checkdiffpairvsdiffpair=TRUE checkxsignals=TRUE checkothers=TRUE targetsourcename=NetR48_1-QSPI_SCLK_PP1
MatchedLengths USB [InDifferentialPairClass('90E')] p2: tolerance=2.5 checknetsindiffpair=TRUE checkdiffpairvsdiffpair=FALSE checkxsignals=FALSE checkothers=FALSE
MatchedLengths LM_DCA [InxSignalClass('DCA_JTAG')] p3: tolerance=50 checknetsindiffpair=FALSE checkdiffpairvsdiffpair=TRUE checkxsignals=TRUE checkothers=TRUE targetsourcename=DCA_TMS-NetJ6_8_PP1
MatchedLengths ANTENNA_RX [InNetClass('ANTENNA_RX SIGNALS')] p4: tolerance=1 checknetsindiffpair=FALSE checkdiffpairvsdiffpair=TRUE checkxsignals=TRUE checkothers=TRUE
MatchedLengths ANTENNA_TX [InNetClass('ANTENNA_TX SIGNALS')] p5: tolerance=1 checknetsindiffpair=FALSE checkdiffpairvsdiffpair=TRUE checkxsignals=TRUE checkothers=TRUE
MatchedLengths LM_XDS [InxSignalClass('XDS_JTAG')] p6: tolerance=50 checknetsindiffpair=FALSE checkdiffpairvsdiffpair=TRUE checkxsignals=TRUE checkothers=TRUE targetsourcename=XDS_TCK-NetR122_1_PP1
MatchedLengths DCA_LP_SPIA [InxSignalClass('DCA_LP_SPIA')] p7: tolerance=20 checknetsindiffpair=FALSE checkdiffpairvsdiffpair=TRUE checkxsignals=TRUE checkothers=TRUE targetsourcename=DCA_LP_HOST_INTR_1-NetJ6_10_PP1
MatchedLengths DCA_LP_FTDI [InxSignalClass('DCA_LP_FTDI')] p8: tolerance=20 checknetsindiffpair=FALSE checkdiffpairvsdiffpair=TRUE checkxsignals=TRUE checkothers=TRUE
MatchedLengths XDS_DCA_JTAG [InxSignalClass('XDS_DCA_JTAG')] p9: tolerance=50 checknetsindiffpair=FALSE checkdiffpairvsdiffpair=TRUE checkxsignals=TRUE checkothers=TRUE targetsourcename=XDS_DCA_TCK_PP3
MatchedLengths LM_FTDI_SPI [InxSignalClass('FTDI_SPI')] p10: tolerance=10 checknetsindiffpair=FALSE checkdiffpairvsdiffpair=TRUE checkxsignals=TRUE checkothers=TRUE targetsourcename=FTDI_SPI_CLK-FTDI_SPICLK_PP1
MatchedLengths LM_SPIB [InxSignalClass('SPIB')] p11: tolerance=10 checknetsindiffpair=FALSE checkdiffpairvsdiffpair=TRUE checkxsignals=TRUE checkothers=TRUE targetsourcename=I2C_SCL_SPIB_CLK_PP1
MatchedLengths "XDSET_DIFF PAIR" [InxSignalClass('XDSET DIFF PAIR')] p12: tolerance=2.5 checknetsindiffpair=TRUE checkdiffpairvsdiffpair=FALSE checkxsignals=FALSE checkothers=FALSE
MatchedLengths DIFF_LVDS [InxSignalClass('LVDS')] p13: tolerance=2 checknetsindiffpair=TRUE checkdiffpairvsdiffpair=FALSE checkxsignals=FALSE checkothers=FALSE
MatchedLengths DIFF_LVDS_GRP [InxSignalClass('LVDS')] p14: tolerance=1.5 checknetsindiffpair=FALSE checkdiffpairvsdiffpair=TRUE checkxsignals=TRUE checkothers=TRUE targetsourcename=RADAR_LVDS_CLKP-NetJ6_44_PP2
MinimumAnnularRing MinimumAnnularRing_ThermalPadVias [IsVia and InAnyComponent] p1: minimumring=3.9
MinimumAnnularRing [All] p2: minimumring=3.9
MinimumSolderMaskSliver MinimumSolderMaskSliver_Logo [InComponentClass('Logo') vs InComponentClass('Logo')] p1: minsoldermaskwidth=0.7
MinimumSolderMaskSliver [All] p2: minsoldermaskwidth=3.5
PlaneConnect [All] p1: planeconnectstyle=Relief reliefexpansion=10 reliefentries=4 reliefconductorwidth=10 reliefairgap=10
PolygonConnect [All] p1: connectstyle=Direct reliefconductorwidth=10 reliefentries=4 polygonreliefangle="90 Angle" airgapwidth=10
RoomDefinition BGA1 [False vs False] p1: confinementstyle=ConfineIn formatcopy=TRUE lockcomponents=FALSE outline 2025,2953 2501,2953 2501,2437.73 2025,2437.73
RoutingVias [All] p1: holewidth=12.2 width=22.4 viastyle="Through Hole" minholewidth=5.9 minwidth=14 maxholewidth=20 maxwidth=40 useviatemplates=TRUE viatemplateguid#1={E2911D76-663B-4C28-95AD-0C427F46FF10} viatemplateguid#2={9E0678DD-4FAF-413B-9962-B5BD3FFA5594} viatemplateguid#3={C5C631FA-2ECB-421D-928B-ED62B3931DBB} viatemplateguid#4={A1332120-9D96-4F23-AB61-4F38D569CF95} viatemplateguid#5={F72E5EFE-427D-4991-B7D8-F79151036B1D} viatemplatename#1=v46h20m0mx0(Tol8-8) viatemplatename#2=v46h20m0mx0(Tol8-8)(1) viatemplatename#3=v46h20m0mx92735(Tol8-8) viatemplatename#4=v35h18(Tol8-8) viatemplatename#5=v35h18m0(Tol8-8)
SMDToCorner [All] p1: distance=25000
SilkToBoardRegionClearance [Not ((IsComment or IsDesignator) And (Hide <> 'False')) and not InRegion(1000,500,4000,800)] p1:
SilkToSilkClearance [All] p1: silktosilkclearance=3
SilkToSolderMaskClearance SilkToSolderMaskClearance_OutLine [istrack and InAnyComponent] p1: minsilkscreentomaskgap=0 clearancetoexposedcopper=FALSE
SilkToSolderMaskClearance SilkscreenOverComponentPads [IsPad] p2: minsilkscreentomaskgap=3 clearancetoexposedcopper=FALSE
SolderMaskExpansion [All] p1: expansion=0 istentingtop=FALSE
UnRoutedNet [All] p1: checkbadconnections=TRUE
Width PWR [InNetClass('POWER')] p1: maxlimit=100 minlimit=6 preferedwidth=15 midlayer1_minwidth=10 midlayer1_maxwidth=10 midlayer1_prefwidth=10 midlayer4_minwidth=10 midlayer4_maxwidth=10 midlayer4_prefwidth=10 minimp=50.000000 maximp=50.000000 favimp=50.000000
Width [All] p2: maxlimit=100 minlimit=4 preferedwidth=15 toplayer_prefwidth=10.8 midlayer1_minwidth=6 midlayer2_minwidth=6 midlayer2_prefwidth=6 midlayer3_minwidth=6 midlayer4_minwidth=6 midlayer5_minwidth=6 midlayer6_minwidth=6 midlayer6_prefwidth=6 bottomlayer_prefwidth=8.7 minimp=50.000000 maximp=50.000000 favimp=50.000000
12 further rules are at their usual default settings.

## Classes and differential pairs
net class "ANTENNA_RX SIGNALS": RX1 RX2 RX3 RX4 RX5 RX6 RX7 RX8
net class "ANTENNA_TX SIGNALS": TX1 TX2 TX3 TX4 TX5 TX6 TX7 TX8
component class PROC207A_Chip_Power: C31 TP22
differential pair class 100E: B_RADAR_LVDS_0 B_RADAR_LVDS_1 B_RADAR_LVDS_CLK B_RADAR_LVDS_FRCLK RADAR_LVDS RADAR_LVDS_1 RADAR_LVDS_CLK RADAR_LVDS_FRCLK
differential pair class 90E: D_FTDI_USBD D_XDSET_1
differential pair class 120E: CAN_FD CAN_FD_B
net class POWER: 5V_IN_USB 12V_DC_JACK CONN_5V FTDI_3V3 FTDI_VBUS FTDI_VCORE MCU_3V3 MCU_5V PMIC_LS_3V3 PMIC_OUT_1V2 PMIC_OUT_1V8 PMIC_OUT_3V3 RADAR_1P2_RF RADAR_1V2 RADAR_1V_RF_OUT RADAR_3V3 REG_1V2 REG_1V8 REG_RF_1V2 USB_5V VCC_3V3 VCC_12V VCC_CAN_3V3 VCC_XDS_3V3 VDDC_1 VSYS_IN
component class PROC207A_XDS110_Interface: C94 C95 C97 C98 C99 C102 C106 C108 C113 C114 C115 C116 C118 C124 C125 C126 C127 R24 R26 R122 R124 R125 R126 R169 R170 R181 R188 R190 R191 R194 R195 R196 R197 R199 R202 R231 R233 R234 R236 R239 R290 S5 U21 U22 Y2
component class PROC207A_USB_PWR_DC_Jack_Switch: C30 C43 C46 C47 C48 C49 C50 C54 C55 C60 C61 C62 C63 C64 C66 C67 C68 C84 C85 C86 D1 D2 D3 D6 D12 J5 J7 L1 L8 L9 ms mx Q2 R1 R4 R9 R20 R23 R27 R33 R35 R36 R72 R73 R74 R75 R172 R174 R179 TP7 TP13 TP14 TP15 U9 U10 U14
component class PROC207A_Temp_Current_sensors_EPROM: C36 C57 C58 C59 C65 C133 R2 R14 R25 R29 R55 R56 R94 R97 R98 R101 R103 R104 R105 R106 R107 R108 R109 R110 R111 R112 R113 R114 R115 R116 R117 R134 R135 R136 R137 R139 R142 R148 R150 R151 R157 R158 R159 R160 R161 R162 R192 R193 R200 R283 U3 U6 U7 U8 U11 U25
component class PROC207A_PMIC: C3 C20 C27 C42 C51 C69 C70 C71 C72 C73 C74 C75 C76 C77 C78 C79 C80 C81 C82 C83 C87 C88 C89 C90 C91 C100 C103 C105 C112 C117 C137 C154 C155 C156 D4 FB1 FB2 FB3 L4 L5 L6 L11 L14 P1 R11 R54 R57 R76 R77 R82 R83 R84 R85 R86 R87 R89 R90 R91 R92 R145 R241 R245 R278 R279 R280 R281 R282 R288 R289 tc TP16 TP17 TP18 TP19 TP20 TP21 U13 U15 U20
component class PROC207A_MUX_CAN_FD: C107 C109 C110 C111 J8 R127 R128 R129 R130 R131 R132 R133 R140 R143 R144 R147 R149 U18 U19
component class PROC207A_I2C_SPI_Connector: C119 C120 J1 J2 J9 J11 J12 J13 J14 ms R154 R155 R156 R163 R164 R166 R173 R175 R176 R177 R178 R180 R182 R183 R198 R201 R210 R211 R212 R221 R222 R223 R224 R232 R238 R240 R254 R285 R286
component class PROC207A_FTDI: C138 C139 C140 C141 C142 C143 C144 C145 C146 C147 C148 C149 C150 C151 C152 C153 C157 C158 D10 J10 L2 L3 L7 R96 R99 R100 R102 R118 R119 R120 R121 R167 R168 R184 R185 R186 R187 R189 R209 R216 R217 R218 R237 R242 R243 R248 R249 R251 R252 R259 R260 U26 U27 U29 Y3
component class PROC207A_Hardware: !PCB "CAUTION HOT SURFACE1" FID1 FID2 FID3 FID4 FID5 FID6 LBL1 Logo1 Logo2 Logo3 Logo4 ZZ1 ZZ2 ZZ3 ZZ4 ZZ5
component class PROC207A_DCA1000_Connector_Reset: C52 C53 C92 C93 C96 D5 D7 D9 D11 D13 J6 Q1 Q3 Q4 R28 R30 R34 R37 R38 R39 R40 R41 R42 R52 R53 R58 R59 R60 R61 R62 R63 R64 R65 R66 R123 R138 R141 R152 R153 R165 R171 R213 R214 R215 R219 R220 R225 R226 R227 R228 R229 R230 R258 R262 R263 R264 R265 R287 S2 S3 S6 U17
component class PROC207A_CAN_LIN_PHY_Interface: C37 C38 C39 C123 C132 D8 J3 J4 R3 R17 R18 R19 R21 R22 R31 R32 R68 R69 R71 R78 R79 R80 R88 R266 R273 U5 U23
component class PROC207A_Analog_MUX_SPI: C56 C135 C136 R10 R12 R253 R271 R272 R274 R275 TP4 U24 U28 U30
component class PROC207A_Analog_Mux_SOP_Ctrl: C40 C41 C104 R5 R6 R7 R8 R13 R15 R16 R43 R67 R70 R95 R203 R204 R205 R206 R207 R208 R235 R244 R277 S1 S4 S7 S8 TP1 U4 U12 U16
component class Logo: Logo1
component class Label: LBL1
component class Header: J1 J2 J3 J4 J8 J9 J13 P1
component class FiducialMark: FID1 FID2 FID3 FID4 FID5 FID6
component class AssemblyNote: ZZ1 ZZ2 ZZ3 ZZ4 ZZ5
component class "PROC207A_Decoupling_caps- QSPI Flash": C1 C2 C4 C5 C6 C7 C8 C9 C10 C11 C12 C13 C14 C15 C16 C17 C18 C19 C21 C22 C24 C25 C26 C34 C35 C44 C45 C121 C128 C130 C131 R44 R45 R46 R47 R48 R49 R50 R51 U2
component class PROC207A_Chip: C32 C33 C134 J15 R81 R93 R146 R246 R247 R250 R255 R256 R257 R261 R267 R268 R269 R270 R276 R284 TP2 TP3 TP5 TP6 TP8 TP9 TP11 TP12 U1 Y1
net class "TX and RX": RX1 RX2 RX3 RX4 RX5 RX6 RX7 RX8 TX1 TX2 TX3 TX4 TX5 TX6 TX7 TX8
differential pair B_RADAR_LVDS_0: +NetJ6_56 -NetJ6_58
differential pair B_RADAR_LVDS_1: +NetJ6_50 -NetJ6_52
differential pair B_RADAR_LVDS_CLK: +NetJ6_44 -NetJ6_46
differential pair B_RADAR_LVDS_FRCLK: +NetJ6_26 -NetJ6_28
differential pair RADAR_LVDS_FRCLK: +RADAR_LVDS_FRCLKP -RADAR_LVDS_FRCLKM
differential pair RADAR_LVDS_CLK: +RADAR_LVDS_CLKP -RADAR_LVDS_CLKM
differential pair RADAR_LVDS_1: +RADAR_LVDS_1P -RADAR_LVDS_1M
differential pair RADAR_LVDS: +RADAR_LVDS_0P -RADAR_LVDS_0M
differential pair D_XDSET_1: +XDSET_1_DP -XDSET_1_DM
differential pair D_FTDI_USBD: +FTDI_USBD_P -FTDI_USBD_N
differential pair CAN_FD: +CAN_FD_H -CAN_FD_L
differential pair CAN_FD_B: +CAN_FD_B_H -CAN_FD_B_L

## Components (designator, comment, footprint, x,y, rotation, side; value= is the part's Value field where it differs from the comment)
C1 "GCM155R71C224KE02D" 0402L 2218.56,2564.55 r0 bottom value=0.22uF
C2 "GCM155R71C224KE02D" 0402L 2258.76,2495.75 r0 bottom value=0.22uF
C3 "CGA4J3X7S1A106K125AE" FP-CGA4J3X7S1A106K125AE_0805-MFG 2275.64,1816 r90 bottom
C4 "GCM155R71C224KE02D" 0402L 2220.86,2894.54 r270 bottom value=0.22uF
C5 "GCM155R71C224KE02D" 0402L 2259.47,2894.38 r270 bottom value=0.22uF
C6 "CGA2B3X7R1H473K050BB" 0402L 2156.51,2873.02 r180 bottom value=0.047uF
C7 "GCM155R71C224KE02D" 0402L 2079.55,2488.18 r90 bottom value=0.22uF
C8 "GCM155R71C224KE02D" 0402L 2016.31,2772.4 r0 bottom value=0.22uF
C9 "GCM188D70E226ME36D" FP-GCM188D70E226ME36D_0603-MFG 2424.32,2811.21 r270 bottom value=22µF
C10 "GCM155R71C224KE02D" 0402L 2419.43,2556.01 r180 bottom value=0.22uF
C11 "GCM155R71C224KE02D" 0402L 2019.45,2919.78 r270 bottom value=0.22uF
C12 "GCM155R71C224KE02D" 0402L 2052.46,2919.78 r270 bottom value=0.22uF
C13 "GCM188D70J106ME36D" FP-GCM188D70J106ME36D_0603-MFG 2039.68,2480.68 r270 bottom
C14 "GCM155R71C224KE02D" 0402L 2299.96,2894.54 r270 bottom value=0.22uF
C15 "GCM188D70J106ME36D" FP-GCM188D70J106ME36D_0603-MFG 1980.65,2924.59 r90 bottom
C16 "GCM155R71C224KE02D" 0402L 2358.5,2489.45 r90 bottom value=0.22uF
C17 "GRT155C71A225KE13D" FP-GRT155C71A225KE13D_0402-MFG 2012.95,2738.83 r0 bottom value=2.2µF
C18 "GRT155R70J105KE01D" FP-GRT155R70J105KE01D_0402-MFG 2343.24,2868.33 r270 bottom
C19 "GCM188D70J106ME36D" FP-GCM188D70J106ME36D_0603-MFG 2469.89,2811.72 r270 bottom
C20 "CGA4J3X7S1A106K125AE" FP-CGA4J3X7S1A106K125AE_0805-MFG 2852.18,1422.09 r180 top
C21 "GCM155R71C224KE02D" 0402L 2113.38,2488.42 r90 bottom value=0.22uF
C22 "GRT155R70J105KE01D" FP-GRT155R70J105KE01D_0402-MFG 2300.14,2817.59 r180 bottom
C24 "GCM188D70E226ME36D" FP-GCM188D70E226ME36D_0603-MFG 2420.01,2689.68 r90 bottom value=22µF
C25 "GCM155R71C224KE02D" 0402L 2134.66,2753.72 r90 bottom value=0.22uF
C26 "GCM155R71C224KE02D" 0402L 2096.2,2688.23 r180 bottom value=0.22uF
C27 "CGA4J3X7S1A106K125AE" FP-CGA4J3X7S1A106K125AE_0805-MFG 3016.47,1341.59 r180 top
C30 "EEHZC1V680XP" SM_RADIAL_6.3BMM 2707.97,743.73 r270 top value=68uF
C31 "GCM155R71H104KE02D" 0402 1938.48,2844.69 r180 top value=0.1uF
C32 "GJM1555C1H4R7BB01D" 0402L 2412.51,2987.12 r270 bottom value=4.7pF
C33 "GJM1555C1H4R7BB01D" 0402L 2470.47,2902.41 r180 bottom value=4.7pF
C34 "GCM155R71H104KE02D" 0402 3287.91,2060.41 r270 bottom value=0.1uF
C35 "CL10B105KA8NNNC" 0603 3357.91,2051.41 r90 bottom
C36 "GCM155R71H104KE02D" 0402 3572.12,1620.13 r90 top value=0.1uF
C37 "GCM155R71H104KE02D" 0402 640.72,2058.23 r90 top value=0.1uF
C38 "GCM155R71H104KE02D" 0402 377.8,2191.85 r180 top value=0.1uF
C39 "GCM155R71H472KA37D" 0402L 254.5,1947.48 r0 top value=4700pF
C40 "GCM155R71H104KE02D" 0402 1441.72,1796.4 r270 top value=0.1uF
C41 "GCM155R71H104KE02D" 0402 916.62,2707.58 r0 top value=0.1uF
C42 "GRT155C71A225KE13D" FP-GRT155C71A225KE13D_0402-MFG 3201.01,508.22 r0 top value=2.2µF
C43 "C3216X7R1H475K160AC" 1206_180L 3058.61,1116.81 r90 top value=4.7uF
C44 "GCM188D70E226ME36D" FP-GCM188D70E226ME36D_0603-MFG 2467.03,2689.89 r270 bottom value=22µF
C45 "GCM155R71C224KE02D" 0402L 2258.76,2528.35 r0 bottom value=0.22uF
C46 "GRM155R61A106ME11D" 0402 3521.32,541.55 r0 top value=10uF
C47 "GRM155R61A106ME11D" 0402 3521.32,493.6 r180 top value=10uF
C48 "GCM155R71H104KE02D" 0402 3530.18,1092.32 r90 top value=0.1uF
C49 "C3216X7R1H475K160AC" 1206_180L 2901.65,754.79 r270 top value=4.7uF
C50 "C3216X7R1H475K160AC" 1206_180L 3321.12,705.41 r270 bottom value=4.7uF
C51 "GCM155C71A105KE38D" 0402_070 570.67,2254.41 r0 top value=1uF
C52 "GCM155R71H104KE02D" 0402 1054.8,1902.17 r270 top value=0.1uF
C53 "GCM155R71H104KE02D" 0402 1279.64,694.37 r0 top value=0.1uF
C54 "CL10B105KA8NNNC" 0603 2978.36,752.29 r270 top
C55 "GRM31CR61A476KE15L" 1206_180 3416.02,585.47 r270 top value=47uF
C56 "GCM155R71H104KE02D" 0402 3548.6,1545.8 r180 top value=0.1uF
C57 "GCM155R71H104KE02D" 0402 2078.44,2119.35 r180 bottom value=0.1uF
C58 "GCM155R71H104KE02D" 0402 1025.06,2750.58 r90 bottom value=0.1uF
C59 "GCM155R71H104KE02D" 0402 2647.79,1803.73 r90 top value=0.1uF
C60 "GCM155R71H104KE02D" 0402 3039.65,754.29 r270 top value=0.1uF
C61 "GCM155R71H104KE02D" 0402 3256.43,706.22 r270 bottom value=0.1uF
C62 "CL10B105KA8NNNC" 0603 3106.88,679.78 r0 bottom
C63 "GCM155R71H104KE02D" 0402 3477.09,1092.92 r90 top value=0.1uF
C64 "C1206C106J3RACAUTO" 1206_180 3100.49,775.87 r0 bottom value=10uF
C65 "GCM155R71H104KE02D" 0402 292,2468.79 r180 top value=0.1uF
C66 "GCM155C71A105KE38D" 0402_070 3302.06,742.87 r270 top value=1uF
C67 "GCM155R71H104KE02D" 0402 3255.7,742.86 r90 top value=0.1uF
C68 "GCM155C71A105KE38D" 0402_070 3175.93,620.03 r270 top value=1uF
C69 "GCM155R71H104KE02D" 0402 2103.65,1294.85 r0 top value=0.1uF
C70 "GRM31CR70J226ME19K" FP-GRM31CR70J226ME19K_1206-MFG 1876.51,1347.76 r90 top value=22µF
C71 "GRM31CR70J226ME19K" FP-GRM31CR70J226ME19K_1206-MFG 1785.63,1343.83 r90 top value=22µF
C72 "GRM31CR60J476ME19L" 1206_180 1737.56,1478.07 r180 top value=47uF
C73 "CL10B105KA8NNNC" 0603 2046.45,1434.71 r180 top
C74 "C3216X7R1H475K160AC" 1206_180L 2241.95,1169.04 r0 top value=4.7uF
C75 "CGA4J3X7S1A106K125AE" FP-CGA4J3X7S1A106K125AE_0805-MFG 2016.35,1341.21 r270 top
C76 "CGA4J3X7S1A106K125AE" FP-CGA4J3X7S1A106K125AE_0805-MFG 2489.12,1334.37 r90 top
C77 "CGA4J3X7S1A106K125AE" FP-CGA4J3X7S1A106K125AE_0805-MFG 2317.6,1497.45 r270 top
C78 "CGA4J3X7S1A106K125AE" FP-CGA4J3X7S1A106K125AE_0805-MFG 2313.56,1305.9 r90 top
C79 "GRT155C71A225KE13D" FP-GRT155C71A225KE13D_0402-MFG 2116.03,1479.72 r180 bottom value=2.2µF
C80 "GRM31CR70J226ME19K" FP-GRM31CR70J226ME19K_1206-MFG 2392.62,1663.91 r180 bottom value=22µF
C81 "GRM31CR70J226ME19K" FP-GRM31CR70J226ME19K_1206-MFG 2394.88,1763.88 r180 bottom value=22µF
C82 "GRM31CR60J476ME19L" 1206_180 2190.65,1786.6 r90 bottom value=47uF
C83 "CGA4J3X7S1A106K125AE" FP-CGA4J3X7S1A106K125AE_0805-MFG 2495.02,1502.19 r270 top
C84 "GCM155C71A474KE36D" 0402L 3521.75,453.94 r180 top value=0.47uF
C85 "GCM155R71C224KE02D" 0402L 3522.17,417.4 r0 top value=0.22uF
C86 "GRT188R61A106KE13D" 0603S 3862.11,137.95 r90 top value=10uF
C87 "GRT155C71A225KE13D" FP-GRT155C71A225KE13D_0402-MFG 2107.54,1493.69 r180 top value=2.2µF
C88 "CL10B105KA8NNNC" 0603 2139.79,1318.3 r0 bottom
C89 "GRM31CR70J226ME19K" FP-GRM31CR70J226ME19K_1206-MFG 2637.11,1340.55 r90 top value=22µF
C90 "GRM31CR70J226ME19K" FP-GRM31CR70J226ME19K_1206-MFG 2715.48,1342.95 r90 top value=22µF
C91 "GRM31CR70J226ME19K" FP-GRM31CR70J226ME19K_1206-MFG 2844,1495.98 r180 top value=22µF
C92 "GCM155C71A474KE36D" 0402L 2845.54,630.68 r90 bottom value=0.47uF
C93 "GCM155C71A105KE38D" 0402_070 2806.72,631.98 r90 bottom value=1uF
C94 "GCM155R71H104KE02D" 0402 1639.64,1634.65 r270 bottom value=0.1uF
C95 "GCM155R71H104KE02D" 0402 1663.56,2183.52 r270 bottom value=0.1uF
C96 "GRT188R61A106KE13D" 0603S 2763.45,640.16 r270 bottom value=10uF
C97 "CC0402DRNPO9BN8R0" 0402L 1681.09,1771.62 r90 bottom value=8pF
C98 "CC0402DRNPO9BN8R0" 0402L 1681.09,1852.82 r270 bottom value=8pF
C99 "GCM155R71H104KE02D" 0402 853.37,1492.45 r0 bottom value=0.1uF
C100 "CL10B105KA8NNNC" 0603 2336.97,1526.22 r0 bottom
C102 "GCM155R71E103KA37D" 0402L 857.31,1537.45 r0 bottom value=0.01uF
C103 "GRM31CR60J476ME19L" 1206_180 3024.11,1260.49 r180 top value=47uF
C104 "GCM155R71H104KE02D" 0402 1137.8,2016.73 r90 top value=0.1uF
C105 "GRT155C71A225KE13D" FP-GRT155C71A225KE13D_0402-MFG 3112.29,449.33 r270 top value=2.2µF
C106 "GCM155R71H104KE02D" 0402 897.91,2114.19 r0 bottom value=0.1uF
C107 "GCM155R71H104KE02D" 0402 1223.43,2886.81 r90 top value=0.1uF
C108 "GCM155C71A105KE38D" 0402_070 1431.68,1690.92 r180 top value=1uF
C109 "GCM155R71H104KE02D" 0402 377.63,1780.14 r0 top value=0.1uF
C110 "GCM155R71H104KE02D" 0402 632.96,1643.62 r90 top value=0.1uF
C111 "GCM155R71H472KA37D" 0402L 254.33,1535.77 r0 top value=4700pF
C112 "GRT155C71A225KE13D" FP-GRT155C71A225KE13D_0402-MFG 358.31,2273.11 r270 top value=2.2µF
C113 "GCM155R71H104KE02D" 0402 1294.66,2322.53 r270 bottom value=0.1uF
C114 "GCM155C71A105KE38D" 0402_070 1658,1999.25 r270 bottom value=1uF
C115 "GCM155R71E103KA37D" 0402L 923.42,1817.76 r90 bottom value=0.01uF
C116 "GCM155R71H104KE02D" 0402 913.07,1954.87 r270 bottom value=0.1uF
C117 "CGA4J3X7S1A106K125AE" FP-CGA4J3X7S1A106K125AE_0805-MFG 1950.85,1340.58 r270 top
C118 "GCM155R71E103KA37D" 0402L 903.11,1693.47 r0 bottom value=0.01uF
C119 "GCM155C71A474KE36D" 0402L 505.82,1360.82 r270 bottom value=0.47uF
C120 "GCM155C71A474KE36D" 0402L 712.98,1395.56 r180 top value=0.47uF
C121 "GCM155R71C224KE02D" 0402L 2344.78,2639.54 r180 bottom value=0.22uF
C123 "GCM155R71H104KE02D" 0402 393.53,937.13 r0 top value=0.1uF
C124 "GRT155C71A225KE13D" FP-GRT155C71A225KE13D_0402-MFG 1724.62,1929.29 r0 bottom value=2.2µF
C125 "GCM155R71H104KE02D" 0402 1729.25,1972.41 r180 bottom value=0.1uF
C126 "GCM155R71H104KE02D" 0402 1169.76,1560.6 r0 bottom value=0.1uF
C127 "GCM155C71A105KE38D" 0402_070 1250.8,1570.32 r0 bottom value=1uF
C128 "GCM155R71E103KA37D" 0402L 2255.59,2639.54 r180 bottom value=0.01uF
C130 "GCM155R71E103KA37D" 0402L 2093.31,2832.9 r90 bottom value=0.01uF
C131 "GCJ21BR71C475KA01L" FP-GCJ21BR71C475KA01L_0805-MFG 2240.33,2445.9 r0 bottom value=4.7µF
C132 "885012005063" 0402 256.77,812.7 r270 top value=220pF
C133 "GCM155R71H104KE02D" 0402 2977.36,1632.77 r90 top value=0.1uF
C134 "GCM155R71C224KE02D" 0402L 1494.18,2705 r0 top value=0.22uF
C135 "GCM155R71H104KE02D" 0402 570.67,3194.63 r90 top value=0.1uF
C136 "GCM155R71H104KE02D" 0402 292.04,3057.1 r180 top value=0.1uF
C137 "C3216X7R1H475K160AC" 1206_180L 2243.16,1085.17 r0 top value=4.7uF
C138 "GCM155R71H104KE02D" 0402 2070,325.5 r0 bottom value=0.1uF
C139 "C1608X7S1A475K080AC" 0603L 1369.13,483.18 r270 bottom value=4.7uF
C140 "GCM155R71H104KE02D" 0402 1230.55,922.74 r90 bottom value=0.1uF
C141 "C1608X7S1A475K080AC" 0603L 1161.74,761.99 r90 bottom value=4.7uF
C142 "GCM155R71H104KE02D" 0402 1211.74,758.05 r270 bottom value=0.1uF
C143 "GCM155R71H104KE02D" 0402 1771.56,589.26 r0 bottom value=0.1uF
C144 "GCM155R71H104KE02D" 0402 1771.71,540.83 r0 bottom value=0.1uF
C145 "C1608X7S1A475K080AC" 0603L 1153.57,895.34 r180 bottom value=4.7uF
C146 "GCM155R71H104KE02D" 0402 1187.43,845.03 r0 bottom value=0.1uF
C147 "GCM1555C1H8R0DA16D" 0402L 1180.53,604 r180 bottom
C148 "GCM1555C1H8R0DA16D" 0402L 1271.04,604 r0 bottom
C149 "CL10B105KA8NNNC" 0603 1637.39,457.21 r0 bottom
C150 "GCM155R71H104KE02D" 0402 1628.16,512.55 r180 bottom value=0.1uF
C151 "CL10B105KA8NNNC" 0603 1846.85,779.53 r180 bottom
C152 "GCM155R71H104KE02D" 0402 1662.22,1139.94 r90 bottom value=0.1uF
C153 "GCM155R71H104KE02D" 0402 1486.9,1128.96 r0 bottom value=0.1uF
C154 "GCM155R71H104KE02D" 0402 2223.45,1256.89 r180 top value=0.1uF
C155 "CGA4J3X7S1A106K125AE" FP-CGA4J3X7S1A106K125AE_0805-MFG 2574.2,1501.16 r90 top
C156 "CGA4J3X7S1A106K125AE" FP-CGA4J3X7S1A106K125AE_0805-MFG 2564.14,1333.58 r270 top
C157 "GRT188R61A106KE13D" 0603S 3827.45,1550.77 r90 top value=10uF
C158 "GCM155R71H104KE02D" 0402 3691.91,1635.41 r180 top value=0.1uF
"CAUTION HOT SURFACE1" "CAUTION HOT SURFACE" IEC_HotSurface_Small 1849.44,1415.02 r180 bottom
D1 "PMEG3020EP,115" SOD-128 3700.11,324.55 r270 top value=30V
D2 "PMEG3050EP,115" SOD-128 3265,1043 r0 top value=30V
D3 "TLMY1100-GS15" FP-TLMY1100-GS15_0603-MFG 1995.51,735.23 r0 top
D4 "SMS3923-040LF" SOD-882 1720.26,949.27 r180 top value=V
D5 "TLMY1100-GS15" FP-TLMY1100-GS15_0603-MFG 1725.45,401.58 r180 top
D6 "TLMY1100-GS15" FP-TLMY1100-GS15_0603-MFG 2790.04,481.14 r180 top
D7 "TLMY1100-GS15" FP-TLMY1100-GS15_0603-MFG 981.05,410.73 r180 top
D8 "PMEG3020EP,115" SOD-128 351.36,808.26 r0 bottom value=30V
D9 "TLMY1100-GS15" FP-TLMY1100-GS15_0603-MFG 454.57,2729.64 r0 top
D10 "TLMY1100-GS15" FP-TLMY1100-GS15_0603-MFG 1976.72,834.24 r0 top
D11 "TLMY1100-GS15" FP-TLMY1100-GS15_0603-MFG 3004.61,464.41 r180 top
D12 "PMEG3020EP,115" SOD-128 3705.8,1371.65 r90 top value=30V
D13 "TLMY1100-GS15" FP-TLMY1100-GS15_0603-MFG 1134.84,685.39 r180 top
Designator6_2 "Comment" BRAKE_WAY_HOLES1X3_CUST 335.43,-39.37 r0 top
Designator6_3 "Comment" BRAKE_WAY_HOLES1X3_CUST 3759.06,-39.33 r180 bottom
Designator6_4 "Comment" BRAKE_WAY_HOLES1X3_CUST 335.43,3764.16 r0 bottom
Designator6_5 "Comment" BRAKE_WAY_HOLES1X3_CUST 3016.74,-39.33 r180 bottom
Designator6_6 "Comment" BRAKE_WAY_HOLES1X3_CUST 1476.64,-39.33 r0 top
Designator6_7 "Comment" BRAKE_WAY_HOLES1X3_CUST 3759.06,3764.2 r180 top
Designator6_8 "Comment" BRAKE_WAY_HOLES1X3_CUST 1476.64,3764.2 r0 bottom
Designator6_9 "Comment" BRAKE_WAY_HOLES1X3_CUST 2617.85,3764.2 r180 top
FB1 "MPZ2012S300ATD25" FP-MPZ2012S300ATD25_0805-MFG 2379.81,1848.8 r180 bottom
FB2 "MPZ2012S300ATD25" FP-MPZ2012S300ATD25_0805-MFG 2788.24,1333.71 r90 top
FB3 "MPZ2012S300ATD25" FP-MPZ2012S300ATD25_0805-MFG 2872.87,1294.03 r0 top
FID1 "Fiducial" Fiducial10-20 104,667 r90 top
FID2 "Fiducial" Fiducial10-20 104,667 r90 bottom
FID3 "Fiducial" Fiducial10-20 3846.1,460.19 r90 bottom
FID4 "Fiducial" Fiducial10-20 741.09,3609.47 r90 bottom
FID5 "Fiducial" FIDUCIAL10-20 741.09,3609.47 r90 top
FID6 "Fiducial" FIDUCIAL10-20 3846.1,460.19 r90 top
FID11 "Fiducial" FIDUCIAL10-20 350,3929.13 r90 top
FID11_1 "Fiducial" FIDUCIAL10-20 3744.49,3929.13 r270 top
FID11_2 "Fiducial" FIDUCIAL10-20 3744.49,-204.34 r270 top
FID11_3 "Fiducial" FIDUCIAL10-20 350,-204.34 r90 top
FID15 "Fiducial" FIDUCIAL10-20 350,3929.13 r0 bottom
FID15_1 "Fiducial" FIDUCIAL10-20 3744.49,3929.13 r180 bottom
FID15_2 "Fiducial" FIDUCIAL10-20 3744.49,-204.34 r180 bottom
FID15_3 "Fiducial" FIDUCIAL10-20 350,-204.34 r0 bottom
J1 "61300311021" Wurth_61300311021 158.07,2469.5 r270 top locked
J2 "PBC07SAAN" Sullins_xxC07SAAN 654.92,119.45 r180 top
J3 "61300311021" Wurth_61300311021 158.23,2051.41 r270 top locked
J4 "61300411021" Wurth_61300411021 158.07,984.5 r270 top locked
J5 "105017-0001" CONN_105017-0001 3983.38,266.35 r90 top locked
J6 "QSH-030-01-L-D-A" Samtec_QSH-030-01-X-D-A 3177.69,447.65 r270 bottom
J7 "PJ-063AH" CUI_PJ-063AH 3793.27,757.12 r0 top locked
J8 "61300311021" Wurth_61300311021 158.07,1639.71 r270 top locked
J9 "61300311121" WURTH_61300311121 721.75,1610.85 r270 top
J10 "105017-0001" CONN_105017-0001 3984.25,1668.38 r90 top
J11 "SSM-110-S-DV" Samtec_SSM-110-x-DV 698.27,932 r270 bottom locked
J12 "SSM-110-S-DV" Samtec_SSM-110-x-DV 2398.27,932 r270 bottom locked
J13 "61300311121" WURTH_61300311121 779.43,2267.59 r0 top
J14 "0022288072" FP-0022288072_HDR7-MFG 49.02,3065.75 r90 top locked
J15 "SOLDER JUMPER" SolderJumper 506.88,1369.43 r180 top
L1 "XGL5050-472MEC" FP-XGL5050-472MEC_SMT2_5MM28_5MM48-MFG 2773.12,1053.73 r180 top value=4.7uH
L2 "BLM15HG601SN1D" 0402L 1121.74,754.11 r270 bottom value="600 ohm"
L3 "BLM15HG601SN1D" 0402L 1180.46,959.67 r270 bottom value="600 ohm"
L4 "LQM2MPZR10MJHL" "FP-LQM2MPZR10MJHL_0806 (2016)-MFG" 1692.11,1372.89 r90 top value=0.1uH
L5 "TFM252012ALVA1R5MTAA" FP-TFM252012ALVA1R5MTAA_1008-MFG 2071.56,1223.05 r180 top value=1.5uH
L6 "TFM201610ALMAR47MTAA" TFM201610ALMA 2406.69,1321.97 r270 top value=470nH
L7 "BLM15HG601SN1D" 0402L 1722.98,463.74 r270 bottom value="600 ohm"
L8 "BLM21PG300SH1D" 0805 3725.28,1536.6 r180 top value="30 ohm"
L9 "BLM21PG300SH1D" 0805 3749.6,166.55 r180 top value="30 ohm"
L11 "TFM201610ALMAR47MTAA" TFM201610ALMA 2404.8,1489.87 r90 top value=470nH
L14 "BLM15PD300SZ1D" 0402L 2103.94,1532.75 r180 top
LBL1 "THT-14-423-10" Label_650x200 1389,3192 r180 bottom
Logo1 "Texas Instruments" TI_Stacked_Overlay_Small 1172,3355 r0 top
Logo2 "CE Mark" CE_Mark_5mm 2276.01,528.07 r0 top
Logo3 "FCC disclaimer" FCC_disclaimer 3437.27,2161.5 r0 top
Logo4 "WEEE logo" WEEE_Minimum 482.9,2640.95 r180 bottom
P1 "TSW-102-07-G-S" TSW-102-07-G-S 272.13,2304.41 r270 top
Q1 "SSM3K35AMFV,L3F" FP-SSM3K35AMFV,L3F_SOT-723-MFG 1806.63,401.58 r180 top
Q2 "BSS123W-7-F" SOT-323 1966.97,657.83 r90 top value=100V
Q3 "SSM3K35AMFV,L3F" FP-SSM3K35AMFV,L3F_SOT-723-MFG 3032.98,403.98 r90 top
Q4 "SSM3K35AMFV,L3F" FP-SSM3K35AMFV,L3F_SOT-723-MFG 1062.23,410.73 r180 top
R1 "MCT06030Z0000ZP500" 0603 3819.95,336.42 r180 top value=0
R2 "CRCW040210K0FKED" 0402L 1978.01,1927.2 r270 bottom value=10.0k
R3 "ERJ-2GE0R00X" FP-ERJ-2GE0R00X_0402-MFG 404.36,1881.85 r180 top value=0
R4 "CRCW040262K0JNED" 0402 3139.58,890.92 r90 top value=62k
R5 "CRCW040210K0FKED" 0402L 1487.66,1812.09 r270 top value=10.0k
R6 "RC0402FR-074K7L" 0402 1360.24,1826.77 r90 top value=4.70k
R7 "CRCW040210K0FKED" 0402L 771.91,2707.74 r0 top value=10.0k
R8 "CRCW040210K0FKED" 0402L 960.27,2346.78 r0 top value=10.0k
R9 "CRCW040210K0FKED" 0402L 3089.8,887.38 r270 top value=10.0k
R10 "CRCW040210K0FKED" 0402L 3146.83,1382.92 r270 bottom value=10.0k
R11 "CRCW0402100KFKED" 0402 3305.55,396.53 r90 top value=100k
R12 "CRCW040210K0FKED" 0402L 3004.74,1408.15 r0 bottom value=10.0k
R13 "CRCW0402750RFKED" 0402L 280.01,644.49 r180 top value=750
R14 "CRCW040210K0FKED" 0402L 1845.75,1991.15 r180 bottom value=10.0k
R15 "ERJ-2GE0R00X" FP-ERJ-2GE0R00X_0402-MFG 874.1,473.74 r90 top value=0
R16 "CRCW0402750RFKED" 0402L 814.41,413.57 r180 top value=750
R17 "CRCW040210K0FKED" 0402L 498.82,810.73 r0 top value=10.0k
R18 "ERJ-2GE0R00X" FP-ERJ-2GE0R00X_0402-MFG 476.37,744.34 r180 top value=0
R19 "ERJ-2GE0R00X" FP-ERJ-2GE0R00X_0402-MFG 479.31,861.92 r180 top value=0
R20 "RC0402FR-074K7L" 0402 3139.44,890.8 r270 bottom value=4.70k
R21 "ERJ-2RKF1001X" 0402 281.69,934.5 r0 top value=1.00k
R22 "CRCW040210K0FKED" 0402L 477.36,709.34 r180 top value=10.0k
R23 "RC0402FR-074K7L" 0402 3089.8,891.32 r270 bottom value=4.70k
R24 "ERJ-2GE0R00X" FP-ERJ-2GE0R00X_0402-MFG 966.13,2319.7 r270 bottom value=0
R25 "ERJ-2GE0R00X" FP-ERJ-2GE0R00X_0402-MFG 1987.58,2127.27 r90 bottom value=0
R26 "ERJ-2GE0R00X" FP-ERJ-2GE0R00X_0402-MFG 803.72,2083.94 r180 bottom value=0
R27 "CRCW040210K0FKED" 0402L 3062.46,641.13 r0 top value=10.0k
R28 "ERJ-2GEJ511X" 0402L 991.94,346.49 r270 top value=510
R29 "ERJ-2GE0R00X" FP-ERJ-2GE0R00X_0402-MFG 1845.52,2066.72 r180 bottom value=0
R30 "MCT06030Z0000ZP500" 0603 2677.55,615.93 r0 bottom value=0
R31 "MCT06030Z0000ZP500" 0603 274.56,1134.5 r0 top value=0
R32 "MCT06030Z0000ZP500" 0603 274.56,1034.5 r0 top value=0
R33 "CRCW040221K5FKED" 0402 3130.93,623.65 r90 top value=21.5k
R34 "ERJ-2GE0R00X" FP-ERJ-2GE0R00X_0402-MFG 2861.48,260.03 r180 bottom value=0
R35 "CRCW040223K7FKED" 0402 3189.08,891.32 r90 bottom value=23.7k
R36 "RT0603BRD0712K1L" 0603 3285.73,871.48 r0 top value=12.1k
R37 "ERJ-2GE0R00X" FP-ERJ-2GE0R00X_0402-MFG 2838.5,743.46 r270 bottom value=0
R38 "ERJ-2GE0R00X" FP-ERJ-2GE0R00X_0402-MFG 2860.87,225.06 r180 bottom value=0
R39 "ERJ-2GE0R00X" FP-ERJ-2GE0R00X_0402-MFG 2875.7,742.57 r270 bottom value=0
R40 "ERJ-2GE0R00X" FP-ERJ-2GE0R00X_0402-MFG 2951.31,229.67 r270 bottom value=0
R41 "ERJ-2GE0R00X" FP-ERJ-2GE0R00X_0402-MFG 2912.47,742.57 r270 bottom value=0
R42 "ERJ-2GE0R00X" FP-ERJ-2GE0R00X_0402-MFG 3041.75,225.06 r0 bottom value=0
R43 "ERJ-2GE0R00X" FP-ERJ-2GE0R00X_0402-MFG 369.87,644.49 r180 top value=0
R44 "CRCW040210K0FKED" 0402 2934.11,2257.96 r0 bottom value=10.0k
R45 "CRCW040233R2FKED" 0402 3316.7,2248 r0 bottom value=33.2
R46 "CRCW040233R2FKED" 0402 2936.48,2138.79 r0 bottom value=33.2
R47 "CRCW040233R2FKED" 0402 2936.08,2198 r0 bottom value=33.2
R48 "CRCW040233R2FKED" 0402 3316.7,2198 r0 bottom value=33.2
R49 "CRCW040210K0FKED" 0402 3426.5,2148 r0 bottom value=10.0k
R50 "RC0402FR-1047K5L" FP-RC0402FR-1047K5L_0402-MFG 2959.24,2098 r0 bottom value=47.5k
R51 "CRCW040233R2FKED" 0402 3315.92,2148 r0 bottom value=33.2
R52 "ERJ-2GE0R00X" FP-ERJ-2GE0R00X_0402-MFG 2947.46,743.02 r270 bottom value=0
R53 "ERJ-2GE0R00X" FP-ERJ-2GE0R00X_0402-MFG 3041.14,260.03 r0 bottom value=0
R54 "CRCW040210K0FKED" 0402L 2087.42,1686.86 r90 top value=10.0k
R55 "ERJ-2GE0R00X" FP-ERJ-2GE0R00X_0402-MFG 3397.95,1601.14 r180 top value=0
R56 "ERJ-2GE0R00X" FP-ERJ-2GE0R00X_0402-MFG 3397.35,1641.74 r180 top value=0
R57 "CRCW040210K0FKED" 0402L 2052.42,1687.86 r270 top value=10.0k
R58 "ERJ-2GE0R00X" FP-ERJ-2GE0R00X_0402-MFG 2981.57,741.49 r270 bottom value=0
R59 "ERJ-2GE0R00X" FP-ERJ-2GE0R00X_0402-MFG 3384.38,786.85 r270 bottom value=0
R60 "ERJ-2GE0R00X" FP-ERJ-2GE0R00X_0402-MFG 3419.05,786.85 r270 bottom value=0
R61 "ERJ-2GE0R00X" FP-ERJ-2GE0R00X_0402-MFG 3458.35,790.2 r270 bottom value=0
R62 "ERJ-2GE0R00X" FP-ERJ-2GE0R00X_0402-MFG 3487.69,692.25 r270 bottom value=0
R63 "ERJ-2GE0R00X" FP-ERJ-2GE0R00X_0402-MFG 3530.7,620.51 r180 bottom value=0
R64 "ERJ-2GEJ511X" 0402L 537.8,2729.64 r0 top value=510
R65 "CRCW040210K0FKED" 0402L 445.71,2769.64 r180 top value=10.0k
R66 "ERJ-2GEJ511X" 0402L 1134.55,394.98 r0 top value=510
R67 "ERJ-2GE0R00X" FP-ERJ-2GE0R00X_0402-MFG 874.72,377.37 r180 top value=0
R68 "CRCW040261R9FKED" 0402L 274.18,2012.17 r90 top value=61.9
R69 "ERJ-2GE0R00X" FP-ERJ-2GE0R00X_0402-MFG 690.72,2102.03 r90 top value=0
R70 "ERJ-2RKF1001X" 0402 1487.89,846.87 r180 top value=1.00k
R71 "CRCW040210K0FKED" 0402L 354.18,1902.17 r90 top value=10.0k
R72 "CRCW040210K0FKED" 0402L 3826.33,336.63 r180 bottom value=10.0k
R73 "CRCW040210K0FKED" 0402L 3062.13,678.47 r180 top value=10.0k
R74 "RC0402FR-074K7L" 0402 3189.26,890.92 r270 top value=4.70k
R75 "RC0402FR-074K7L" 0402 3277.18,871.32 r180 bottom value=4.70k
R76 "ERJ-2RKF1001X" 0402 2263.5,1647.63 r270 top value=1.00k
R77 "ERJ-2GE0R00X" FP-ERJ-2GE0R00X_0402-MFG 2209.46,1584.79 r0 top value=0
R78 "ERJ-2GE0R00X" FP-ERJ-2GE0R00X_0402-MFG 559.82,1951.26 r90 top value=0
R79 "CRCW040261R9FKED" 0402L 274.18,2101.54 r90 top value=61.9
R80 "ERJ-2GE0R00X" FP-ERJ-2GE0R00X_0402-MFG 630.89,2131.85 r180 top value=0
R81 "ERJ-2GE0R00X" FP-ERJ-2GE0R00X_0402-MFG 1824.11,2345.54 r180 top value=0
R82 "CRCW040210K0FKED" 0402L 575.36,2369.21 r0 top value=10.0k
R83 "ERJ-2GE0R00X" FP-ERJ-2GE0R00X_0402-MFG 2266.3,1546.73 r270 top value=0
R84 "CRCW04021K96FKED" 0402 2328.82,1645.17 r270 top value=1.96k
R85 "ERJ-2GE0R00X" FP-ERJ-2GE0R00X_0402-MFG 2067.86,1587.23 r0 top value=0
R86 "CRCW040210K0FKED" 0402L 555.67,2309.53 r90 top value=10.0k
R87 "CRCW040210R2FKED" 0402 1820.42,948.53 r180 top value=10.2
R88 "ERJ-2GE0R00X" FP-ERJ-2GE0R00X_0402-MFG 499.31,778.73 r180 top value=0
R89 "ERJ-2GE0R00X" FP-ERJ-2GE0R00X_0402-MFG 2117.69,1516.47 r0 bottom value=0
R90 "ERJ-2GE0R00X" FP-ERJ-2GE0R00X_0402-MFG 2152.09,1609.83 r0 bottom value=0
R91 "ERJ-2GE0R00X" FP-ERJ-2GE0R00X_0402-MFG 3230.86,299.8 r180 top value=0
R92 "CRCW0402100KFKED" 0402 3227.42,339.8 r0 top value=100k
R93 "CRCW040233R2FKED" 0402 1506.76,2398.61 r90 top value=33.2
R94 "CRCW040210K0FKED" 0402L 1845.75,2030.52 r0 bottom value=10.0k
R95 "CRCW040210K0FKED" 0402L 1236.83,2026.17 r180 top value=10.0k
R96 "ERJ-2GE0R00X" FP-ERJ-2GE0R00X_0402-MFG 1480.25,956.46 r180 top value=0
R97 "CRCW040210K0FKED" 0402L 254.77,2549.1 r270 top value=10.0k
R98 "CRCW040210K0FKED" 0402L 254.77,2638.01 r90 top value=10.0k
R99 "CRCW0402100KFKED" 0402 1570.53,1188.36 r270 bottom value=100k
R100 "ERJ-2GE0R00X" FP-ERJ-2GE0R00X_0402-MFG 1566.21,922.98 r270 top value=0
R101 "CRCW040210K0FKED" 0402L 2018.01,1927.2 r90 bottom value=10.0k
R102 "ERJ-2GE0R00X" FP-ERJ-2GE0R00X_0402-MFG 1620.59,932.52 r180 top value=0
R103 "CRCW040210K0FKED" 0402L 1885.12,1951.15 r180 bottom value=10.0k
R104 "CRCW040210K0FKED" 0402L 832.74,2811.18 r180 bottom value=10.0k
R105 "CRCW040210K0FKED" 0402L 896.69,2983.45 r90 bottom value=10.0k
R106 "CRCW040210K0FKED" 0402L 2843.79,1899.92 r0 top value=10.0k
R107 "CRCW040210K0FKED" 0402L 2779.84,2032.18 r90 top value=10.0k
R108 "ERJ-2GE0R00X" FP-ERJ-2GE0R00X_0402-MFG 1032.81,2841.61 r0 bottom value=0
R109 "ERJ-2GE0R00X" FP-ERJ-2GE0R00X_0402-MFG 2654.95,2034.13 r90 top value=0
R110 "ERJ-2GE0R00X" FP-ERJ-2GE0R00X_0402-MFG 972.26,2983.68 r90 bottom value=0
R111 "ERJ-2GE0R00X" FP-ERJ-2GE0R00X_0402-MFG 2704.27,2032.41 r90 top value=0
R112 "CRCW040210K0FKED" 0402L 936.06,2983.45 r270 bottom value=10.0k
R113 "CRCW040210K0FKED" 0402L 832.74,2851.18 r0 bottom value=10.0k
R114 "CRCW040210K0FKED" 0402L 856.69,2983.45 r270 bottom value=10.0k
R115 "CRCW040210K0FKED" 0402L 2740.47,2032.18 r270 top value=10.0k
R116 "CRCW040210K0FKED" 0402L 2843.79,1859.92 r180 top value=10.0k
R117 "CRCW040210K0FKED" 0402L 2819.84,2032.18 r270 top value=10.0k
R118 "ERJ-2GE0R00X" FP-ERJ-2GE0R00X_0402-MFG 1625.02,868.68 r180 top value=0
R119 "ERJ-2GE0R00X" FP-ERJ-2GE0R00X_0402-MFG 1702.09,859.53 r90 top value=0
R120 "ERJ-2GE0R00X" FP-ERJ-2GE0R00X_0402-MFG 1815.53,661.42 r0 bottom value=0
R121 "ERJ-2GE0R00X" FP-ERJ-2GE0R00X_0402-MFG 1557.21,478.71 r270 bottom value=0
R122 "CRCW040233R2FKED" 0402 1035.35,2348.66 r90 bottom value=33.2
R123 "CRCW040210K0FKED" 0402L 1028.35,1711.08 r270 top value=10.0k
R124 "CRCW040233R2FKED" 0402 1085.33,2348.66 r90 bottom value=33.2
R125 "CRCW040233R2FKED" 0402 1135.31,2331.42 r90 bottom value=33.2
R126 "CRCW040233R2FKED" 0402 1208.2,2335.24 r90 bottom value=33.2
R127 "CRCW040210K0FKED" 0402L 1101.05,2832.5 r180 top value=10.0k
R128 "CRCW040210K0FKED" 0402L 1306.31,2460.72 r270 top value=10.0k
R129 "ERJ-2GE0R00X" FP-ERJ-2GE0R00X_0402-MFG 632.96,1732.61 r90 top value=0
R130 "CRCW040261R9FKED" 0402L 274.01,1600.46 r90 top value=61.9
R131 "ERJ-2GE0R00X" FP-ERJ-2GE0R00X_0402-MFG 404.19,1510.14 r180 top value=0
R132 "ERJ-2GE0R00X" FP-ERJ-2GE0R00X_0402-MFG 506.81,1517.78 r180 top value=0
R133 "ERJ-2GE0R00X" FP-ERJ-2GE0R00X_0402-MFG 404.19,1470.14 r180 top value=0
R134 "WSL1206R0100FEB" FP-WSL1206R0100FEB_1206-MFG 3091.21,1514.68 r180 top value=10m
R135 "CRCW040210K0FKED" 0402L 3172.64,1689.68 r0 top value=10.0k
R136 "CRCW040210K0FKED" 0402L 3108.69,1861.94 r90 top value=10.0k
R137 "ERJ-2GE0R00X" FP-ERJ-2GE0R00X_0402-MFG 2972.57,1720.11 r180 top value=0
R138 "CRCW040210K0FKED" 0402L 1081.26,1711.08 r270 top value=10.0k
R139 "ERJ-2GE0R00X" FP-ERJ-2GE0R00X_0402-MFG 3033.12,1862.17 r90 top value=0
R140 "CRCW040261R9FKED" 0402L 274.01,1689.83 r90 top value=61.9
R141 "ERJ-2GEJ511X" 0402L 1637.22,401.58 r180 top value=510
R142 "CRCW040210K0FKED" 0402L 3069.53,1862.15 r270 top value=10.0k
R143 "ERJ-2GE0R00X" FP-ERJ-2GE0R00X_0402-MFG 570.55,1790.32 r270 top value=0
R144 "CRCW040210K0FKED" 0402L 354.01,1490.46 r90 top value=10.0k
R145 "RC0402FR-074K7L" 0402 2165.39,1225.21 r180 bottom value=4.70k
R146 "CRCW0402100KFKED" 0402L 1644.95,2181.32 r90 top value=100k
R147 "CRCW0402100KFKED" 0402L 1266.78,2460.14 r90 top value=100k
R148 "CRCW040210K0FKED" 0402L 3172.64,1729.68 r180 top value=10.0k
R149 "CRCW0402100KFKED" 0402L 1303.75,2847.79 r180 top value=100k
R150 "CRCW040210K0FKED" 0402L 3148.69,1861.94 r270 top value=10.0k
R151 "CRCW040210K0FKED" 0402L 3404.89,1696.31 r270 top value=10.0k
R152 "ERJ-2GE0R00X" FP-ERJ-2GE0R00X_0402-MFG 3489.84,790.69 r90 bottom value=0
R153 "ERJ-2GE0R00X" FP-ERJ-2GE0R00X_0402-MFG 3520.34,692.25 r90 bottom value=0
R154 "MCT06030Z0000ZP500" 0603 445.42,1334.63 r270 bottom value=0
R155 "MCT06030Z0000ZP500" 0603 734.26,1313 r270 top value=0
R156 "CRCW0402100KFKED" 0402L 417.01,1182 r180 bottom value=100k
R157 "CRCW040210K0FKED" 0402L 415.68,2424.24 r180 top value=10.0k
R158 "CRCW040210K0FKED" 0402L 415.68,2387.24 r0 top value=10.0k
R159 "ERJ-2GE0R00X" FP-ERJ-2GE0R00X_0402-MFG 305.44,2568.79 r180 top value=0
R160 "ERJ-2GE0R00X" FP-ERJ-2GE0R00X_0402-MFG 304.95,2618.33 r180 top value=0
R161 "CRCW040210K0FKED" 0402L 664.87,2528.79 r0 top value=10.0k
R162 "CRCW040210K0FKED" 0402L 645.19,2588.47 r270 top value=10.0k
R163 "CRCW0402100KFKED" 0402L 1096.46,1959.65 r270 top value=100k
R164 "CRCW040210K0FKED" 0402L 1268.16,1201.53 r90 top value=10.0k
R165 "CRCW040210K0FKED" 0402L 1275.7,734.37 r0 top value=10.0k
R166 "CRCW040210K0FKED" 0402L 566.58,324.37 r180 bottom value=10.0k
R167 "CRCW040210K0FKED" 0402L 1654.14,329.65 r180 bottom value=10.0k
R168 "CRCW040210K0FKED" 0402L 1701.29,265.57 r270 bottom value=10.0k
R169 "ERJ-2GEJ101X" 0402L 1674.64,1638.59 r270 bottom value=100
R170 "ERJ-2GE0R00X" FP-ERJ-2GE0R00X_0402-MFG 1697.45,1701.9 r0 bottom value=0
R171 "ERJ-2GEJ511X" 0402L 1809.58,355.83 r180 top value=510
R172 "ERJ-2GEJ511X" 0402L 2004.37,785.23 r180 top value=510
R173 "CRCW0402100KFKED" 0402L 2639.54,1216.29 r0 bottom value=100k
R174 "ERJ-2RKF1001X" 0402 2687.38,481 r0 top value=1.00k
R175 "ERJ-2GE0R00X" FP-ERJ-2GE0R00X_0402-MFG 2433.97,1484.19 r270 bottom value=0
R176 "ERJ-2GE0R00X" FP-ERJ-2GE0R00X_0402-MFG 496.87,1182 r0 bottom value=0
R177 "ERJ-2GE0R00X" FP-ERJ-2GE0R00X_0402-MFG 2599.66,1182 r0 bottom value=0
R178 "ERJ-2GE0R00X" FP-ERJ-2GE0R00X_0402-MFG 496.87,1082 r0 bottom value=0
R179 "ERJ-2GEJ511X" 0402L 1961.06,590.43 r180 top value=510
R180 "ERJ-2GE0R00X" FP-ERJ-2GE0R00X_0402-MFG 496.87,1217 r0 bottom value=0
R181 "ERJ-2GE0R00X" FP-ERJ-2GE0R00X_0402-MFG 994.75,2319.98 r270 bottom value=0
R182 "ERJ-2GE0R00X" FP-ERJ-2GE0R00X_0402-MFG 2585.42,1687.45 r270 top value=0
R183 "ERJ-2GE0R00X" FP-ERJ-2GE0R00X_0402-MFG 2616.19,1082.62 r90 bottom value=0
R184 "CRCW040210K0FKED" 0402L 1782.67,444.06 r180 bottom value=10.0k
